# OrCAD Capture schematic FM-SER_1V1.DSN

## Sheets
1 01. INDEX: title: FM-SER    01. INDEX; rev: 1.1; note: 8000012001
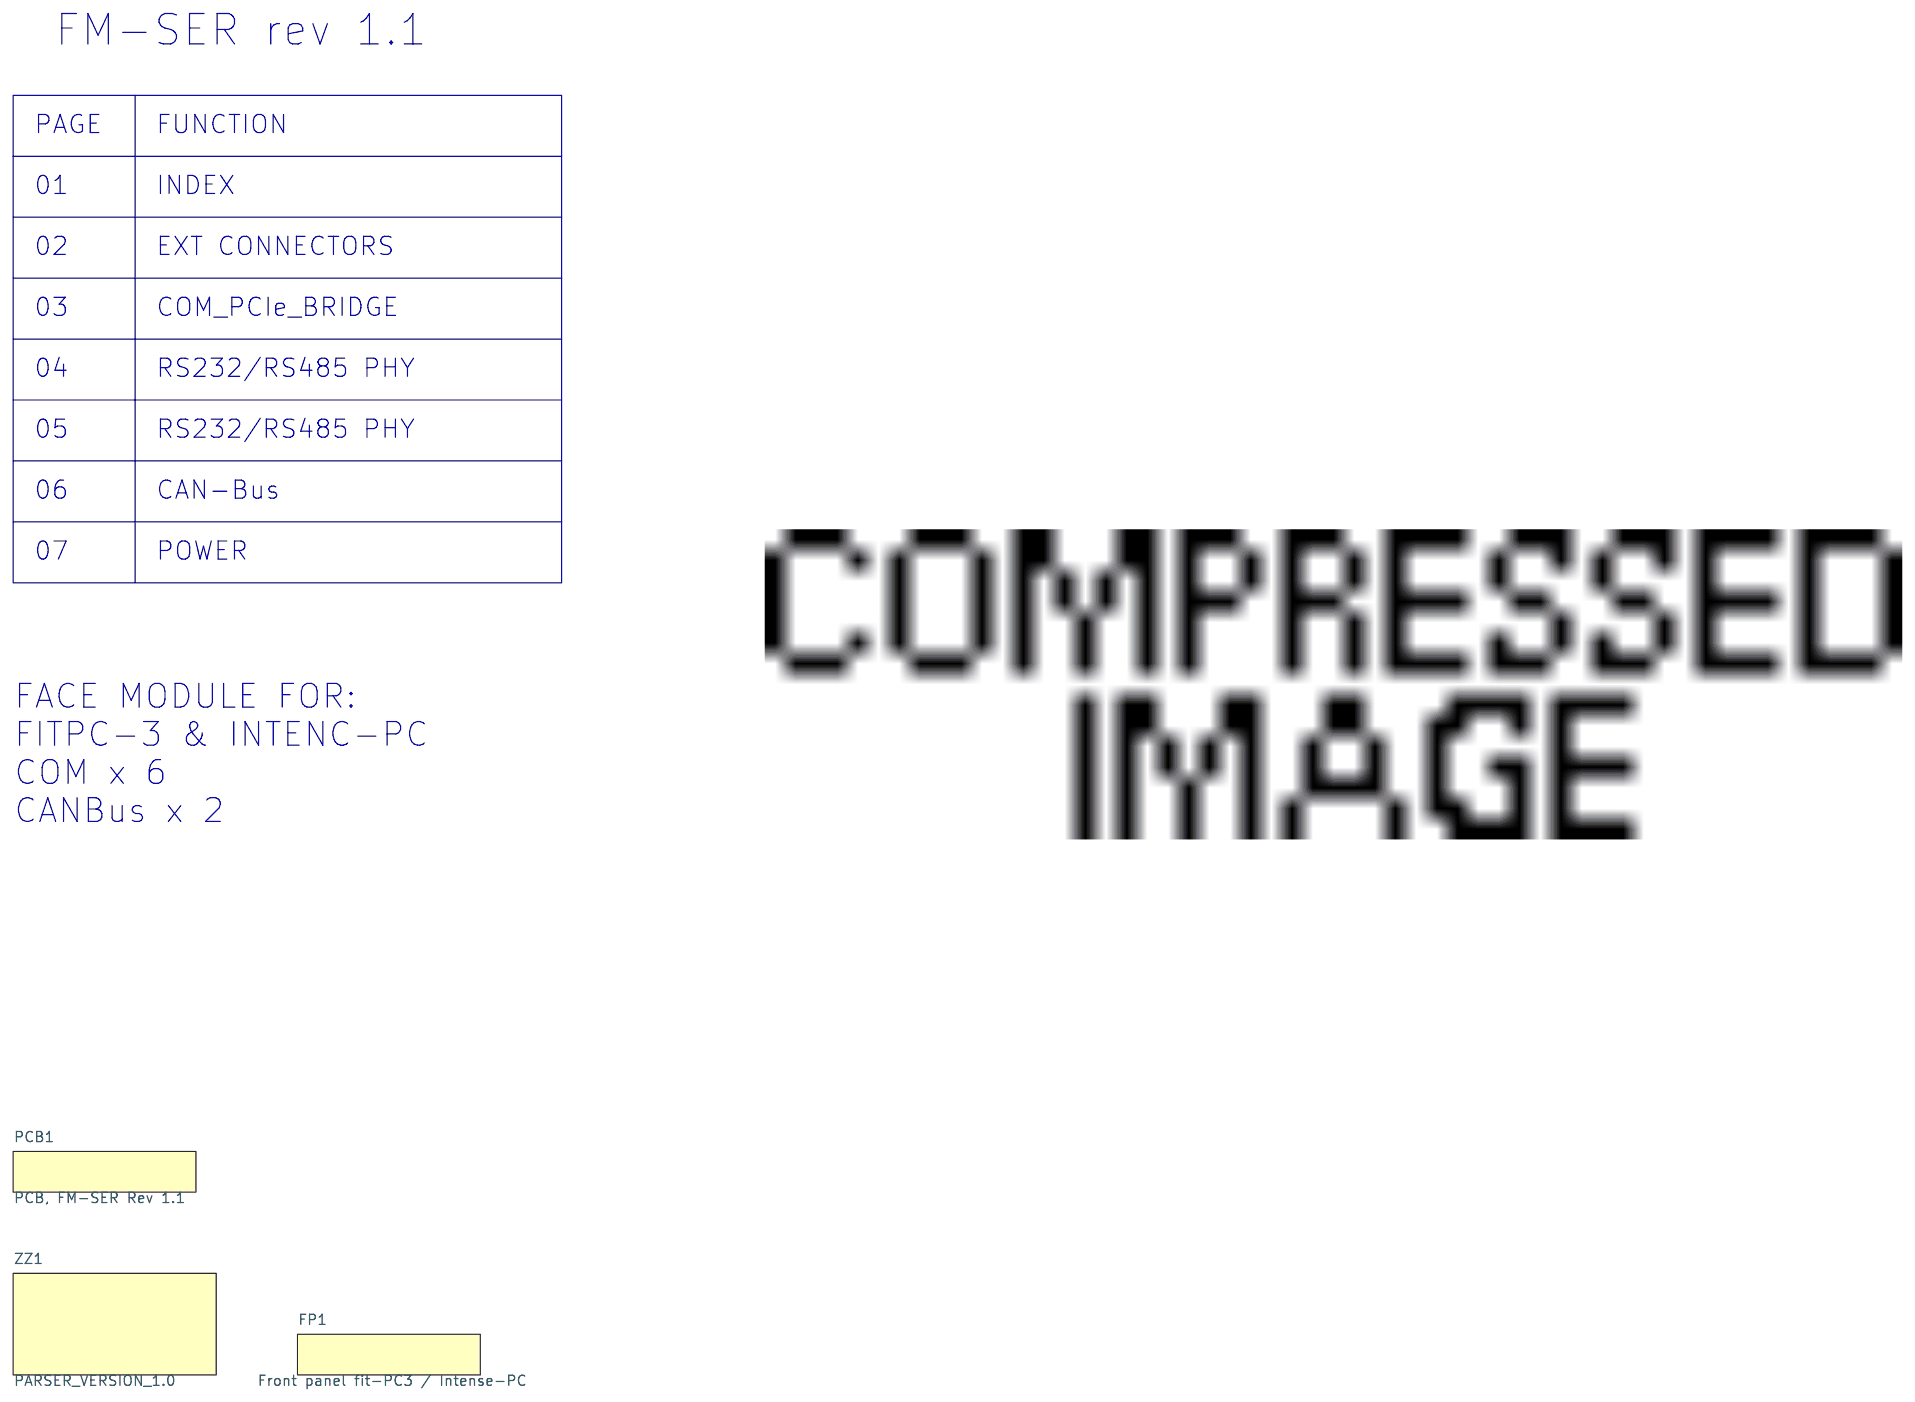
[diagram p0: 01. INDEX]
2 02. EXT CONN: size B; title: FM-SER    02. EXT_CONN
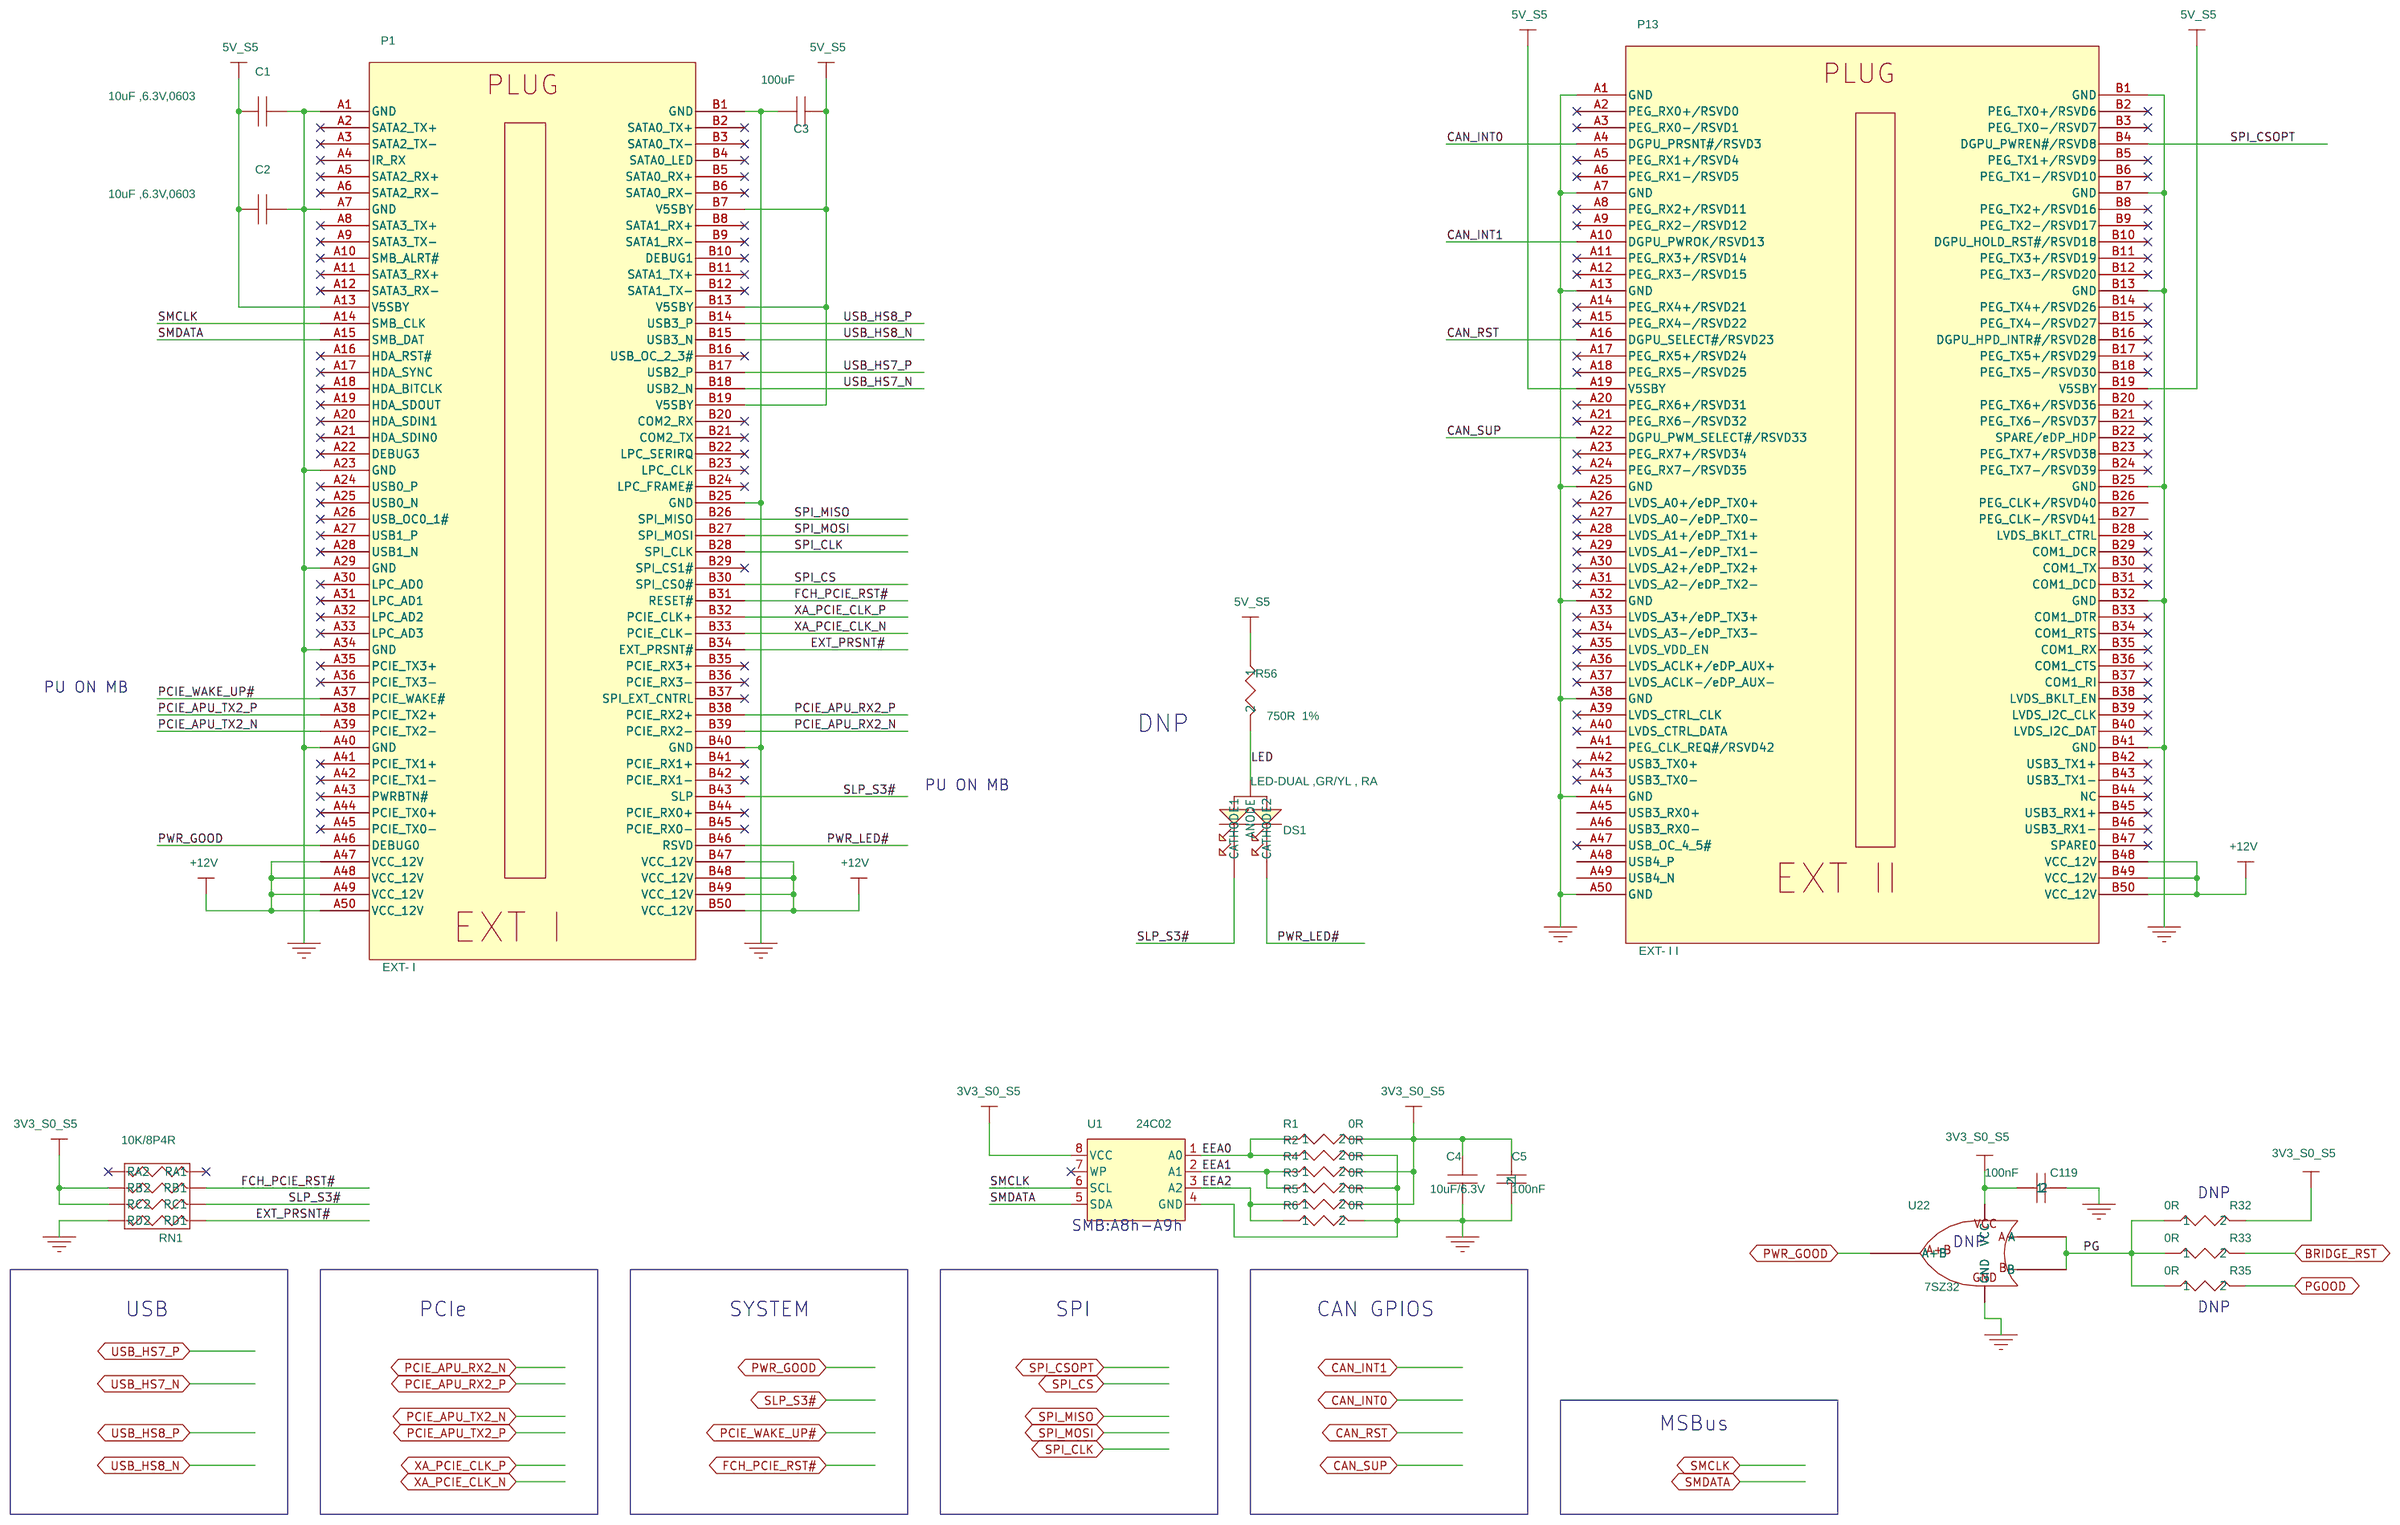
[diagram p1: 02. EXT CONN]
3 03. COM_PCIe_BRIDGE: size B; title: FM-SER  03. COM_PCIe_BRIDGE
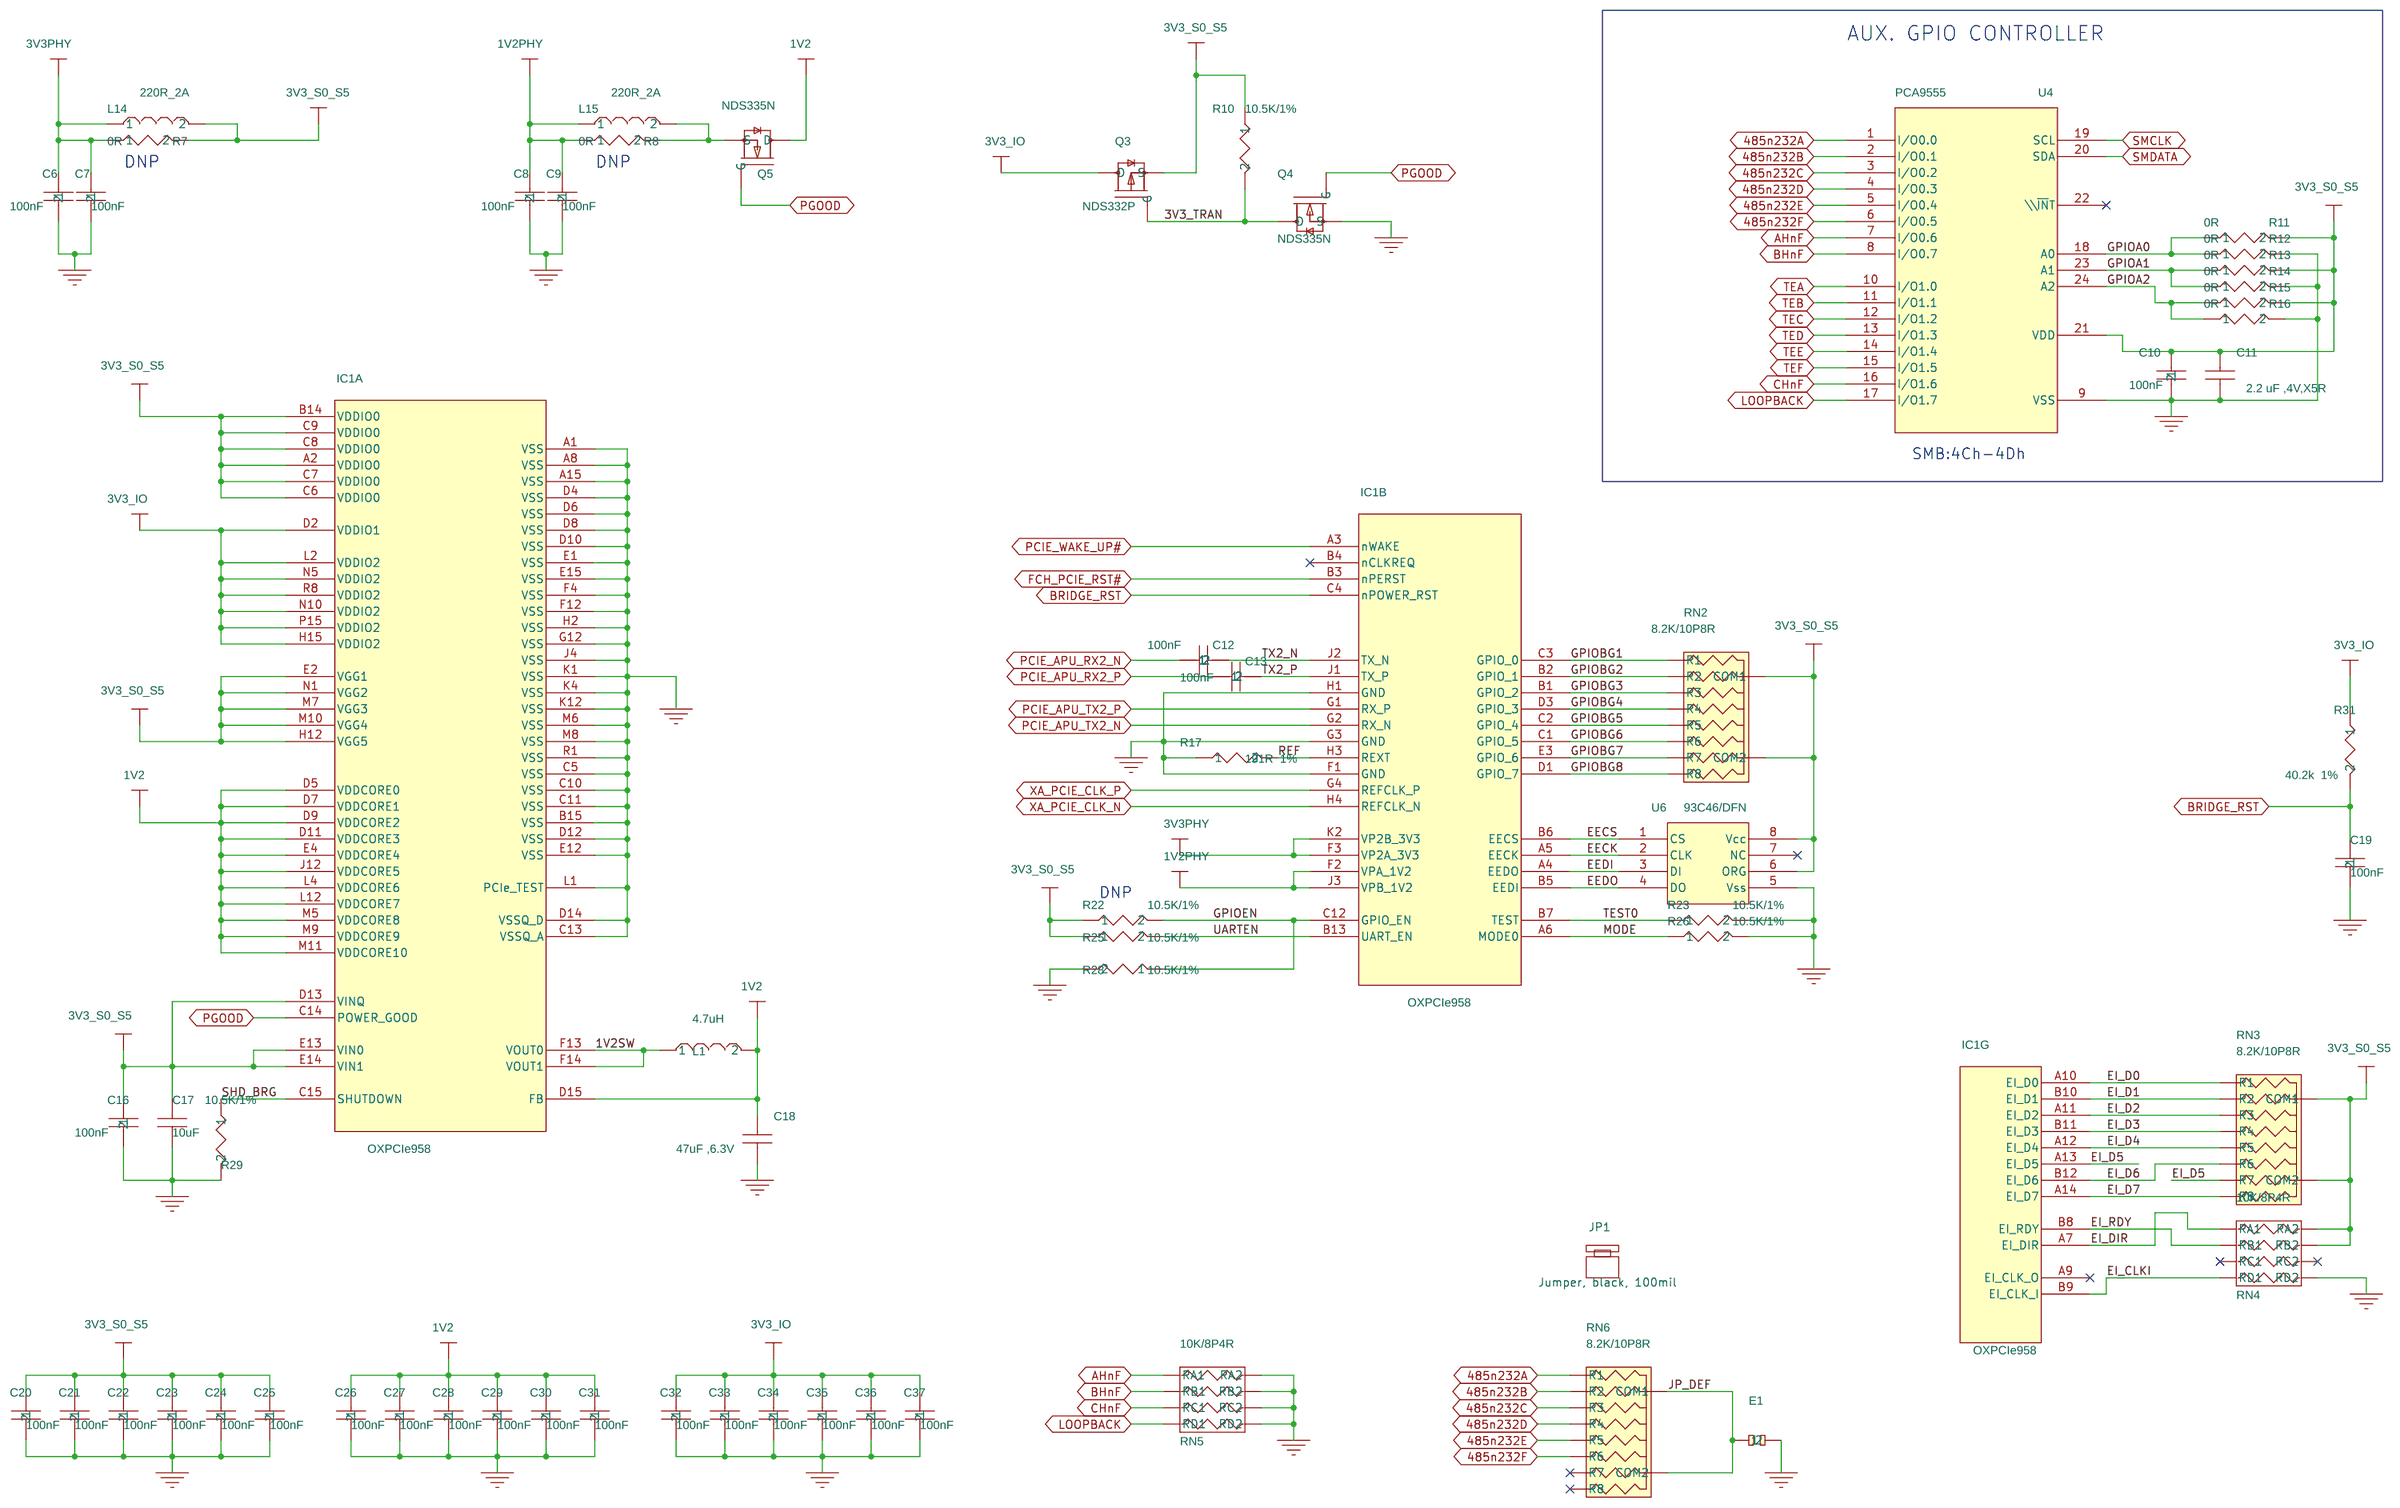
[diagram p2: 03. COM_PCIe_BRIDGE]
4 06. CAN Bus: size C; title: FM-SER    06. POWER
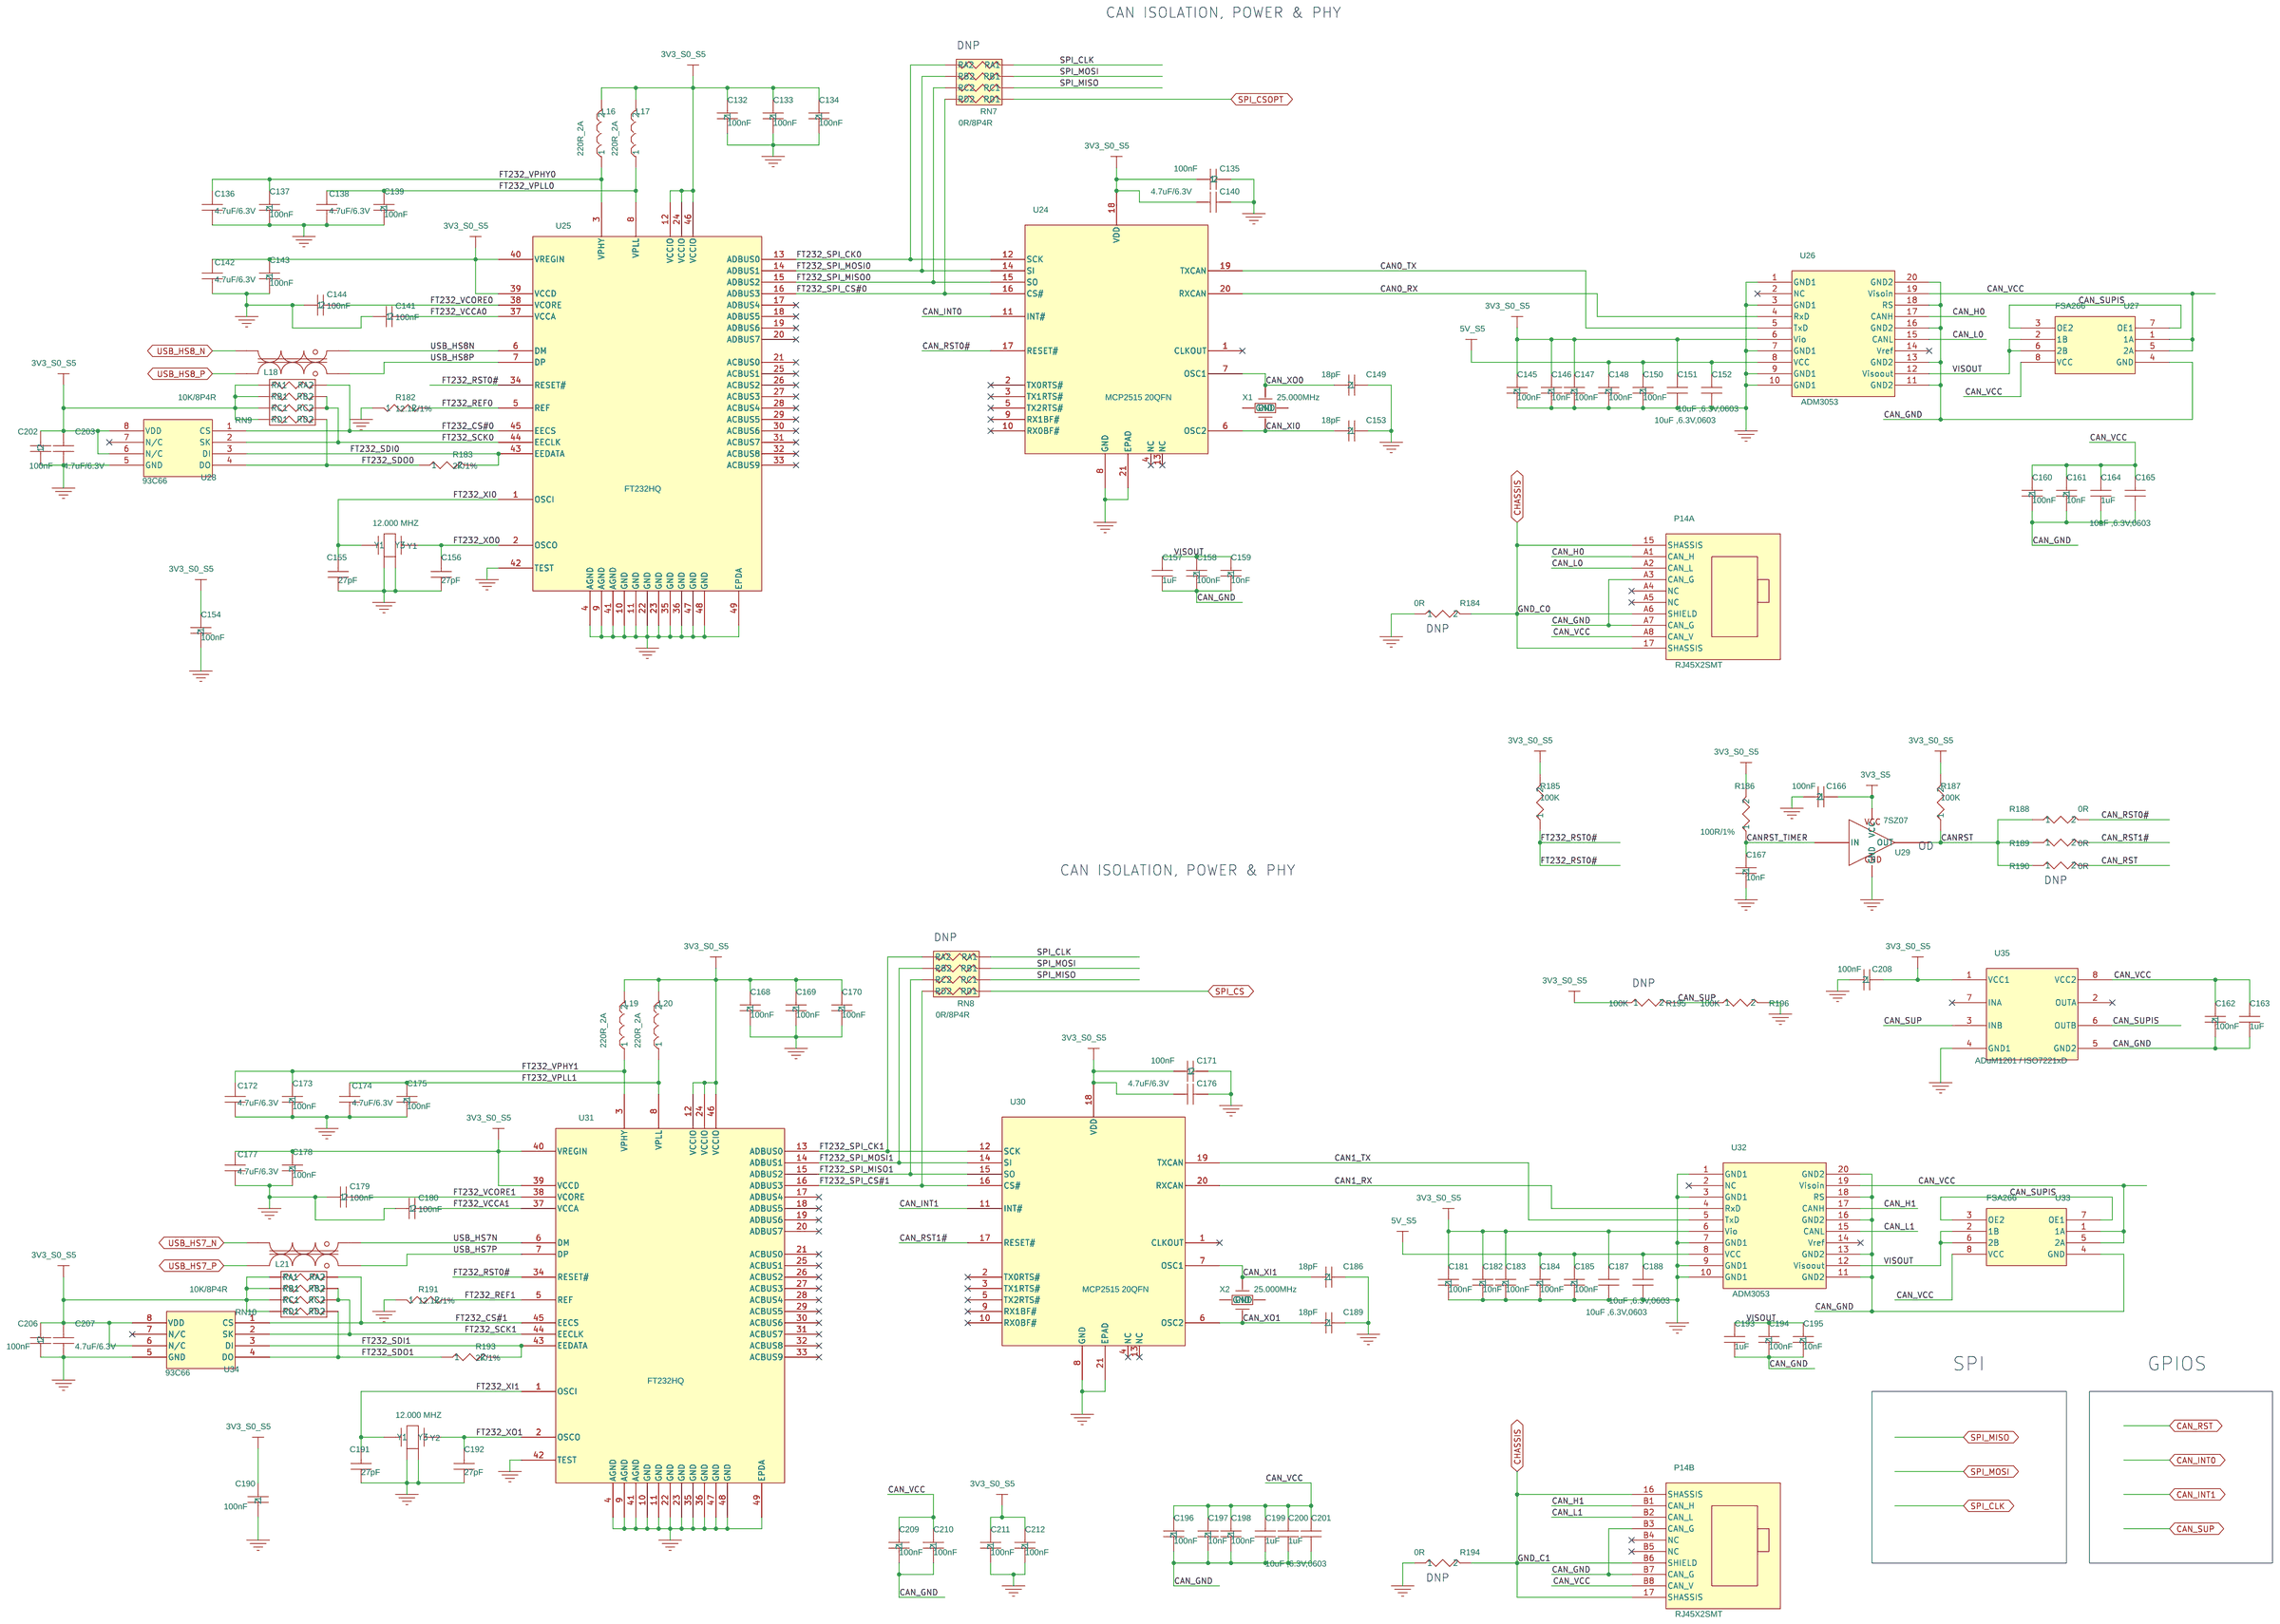
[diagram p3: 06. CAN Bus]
5 07. POWER: size B; title: FM-SER    06. POWER
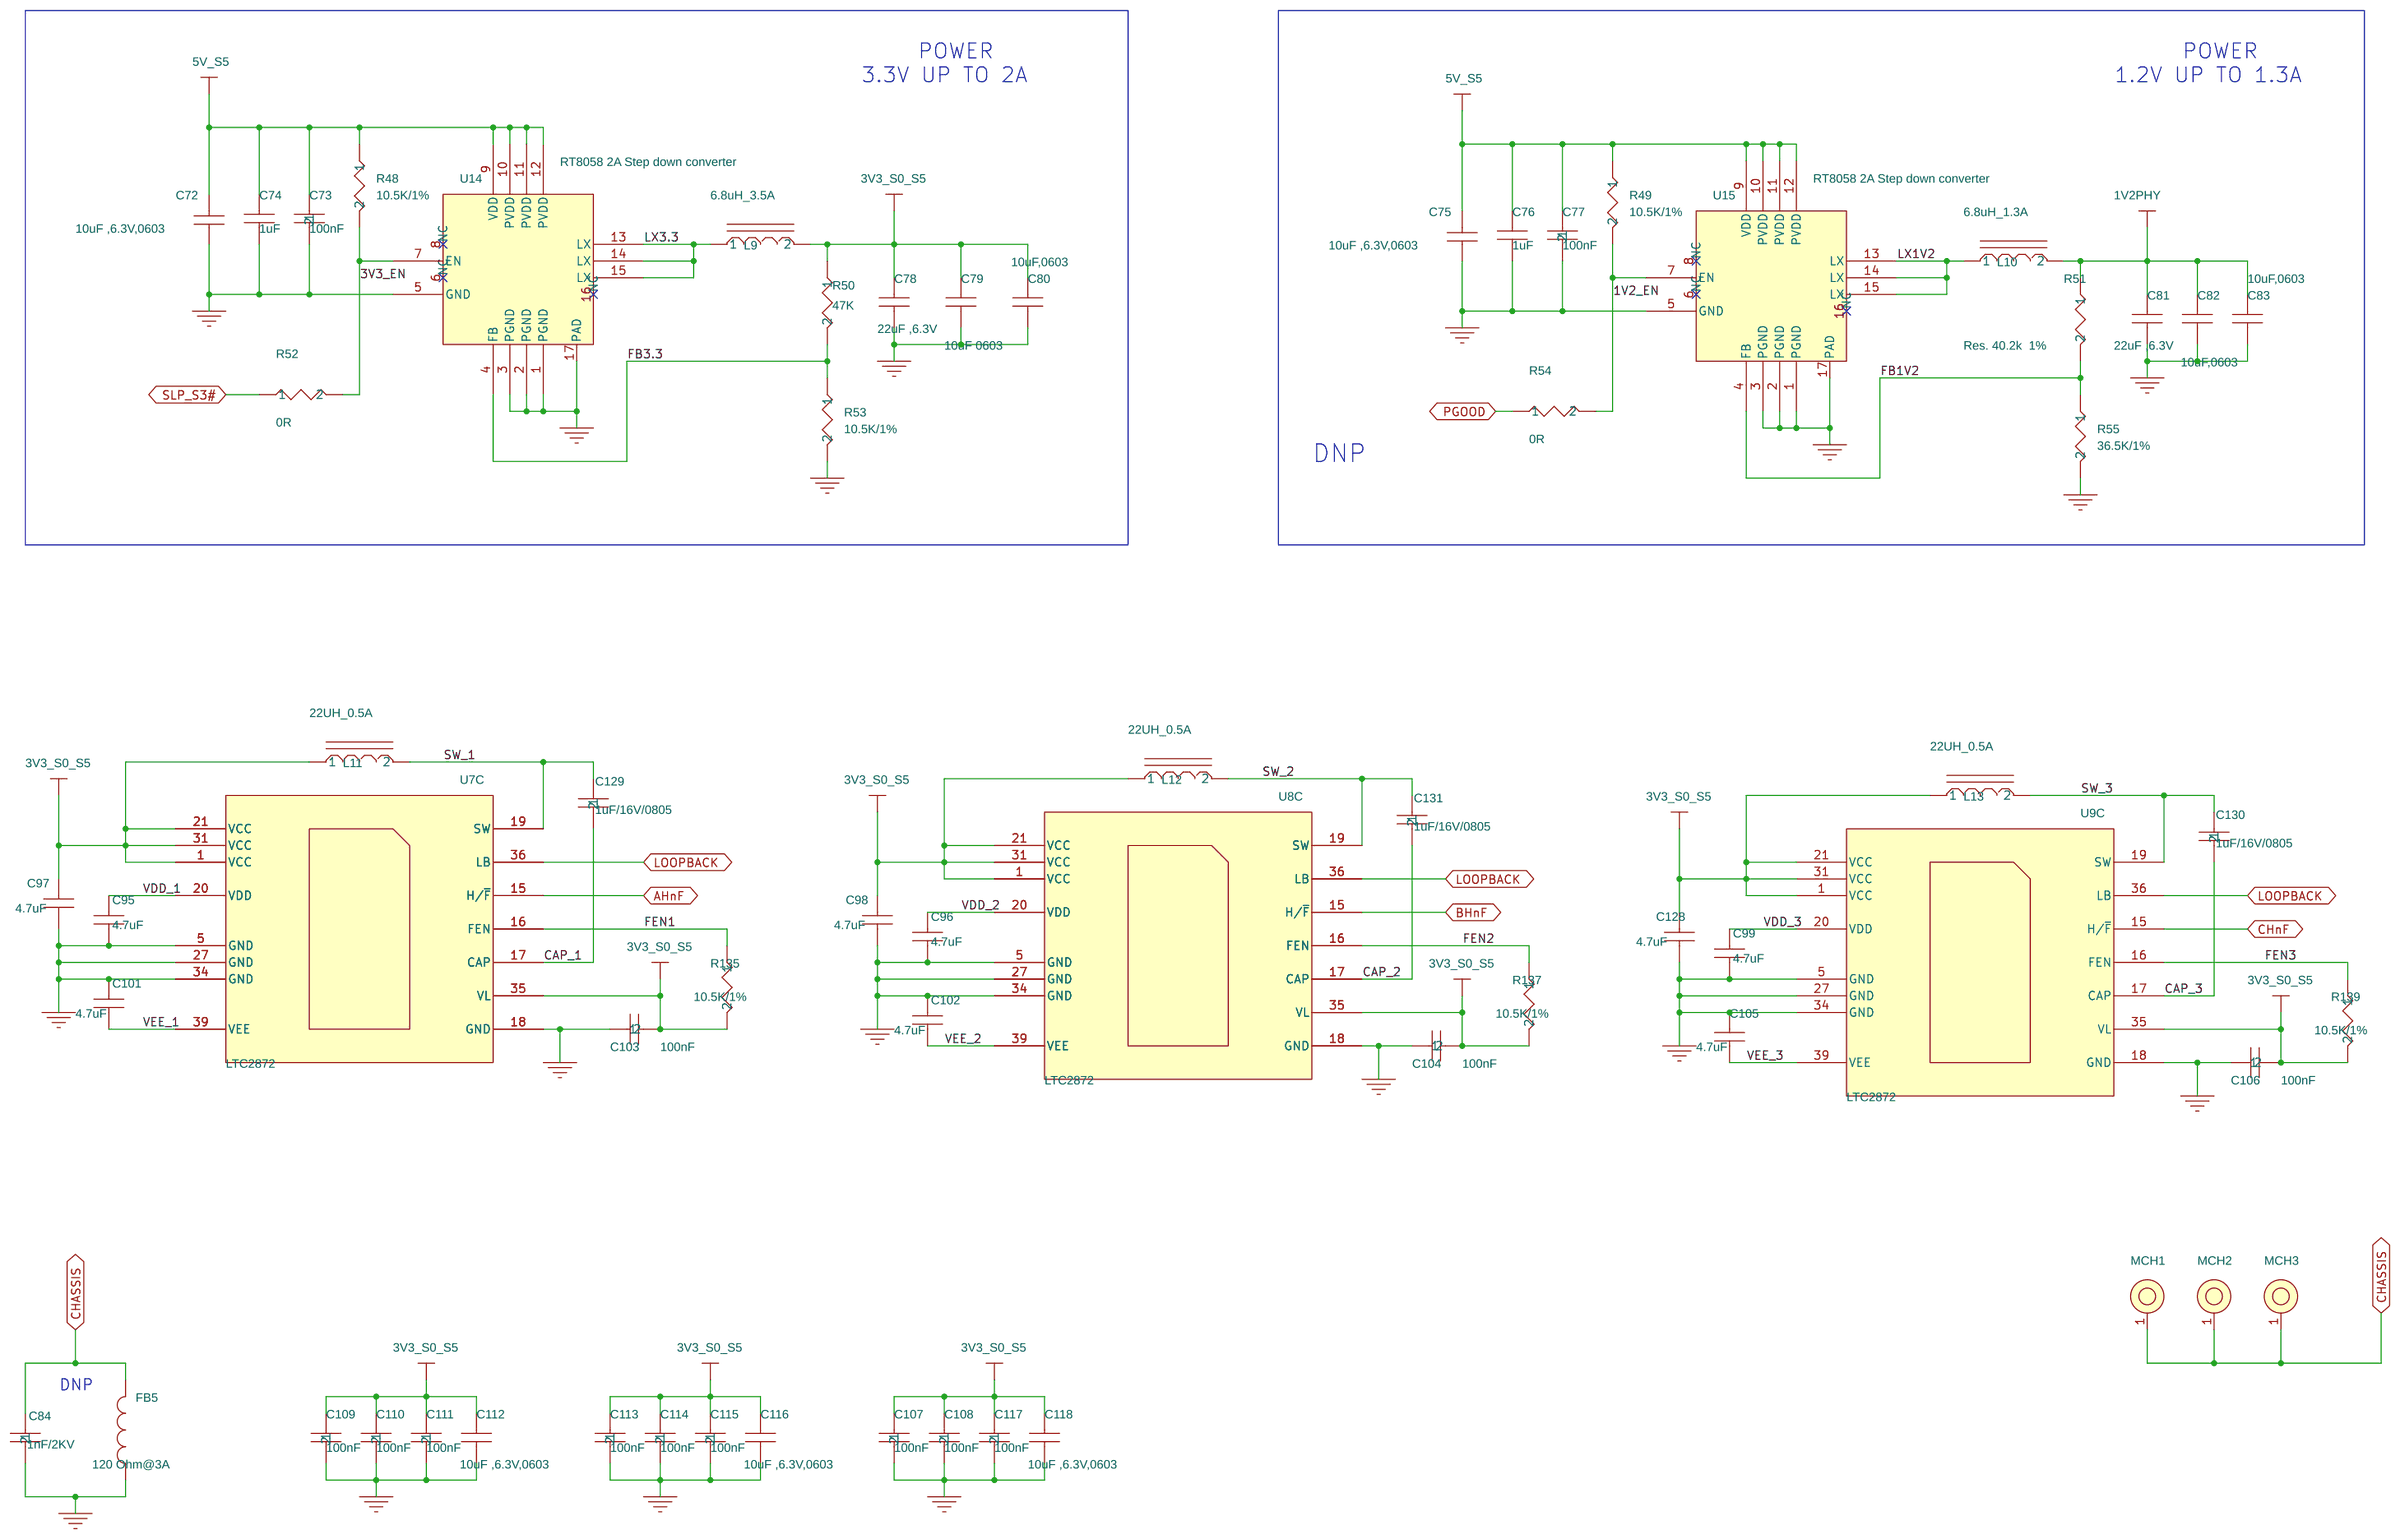
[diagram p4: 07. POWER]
6 04. RS232/RS485 PHY: size B; title: FM-SER    04.RS232/RS485 PHY
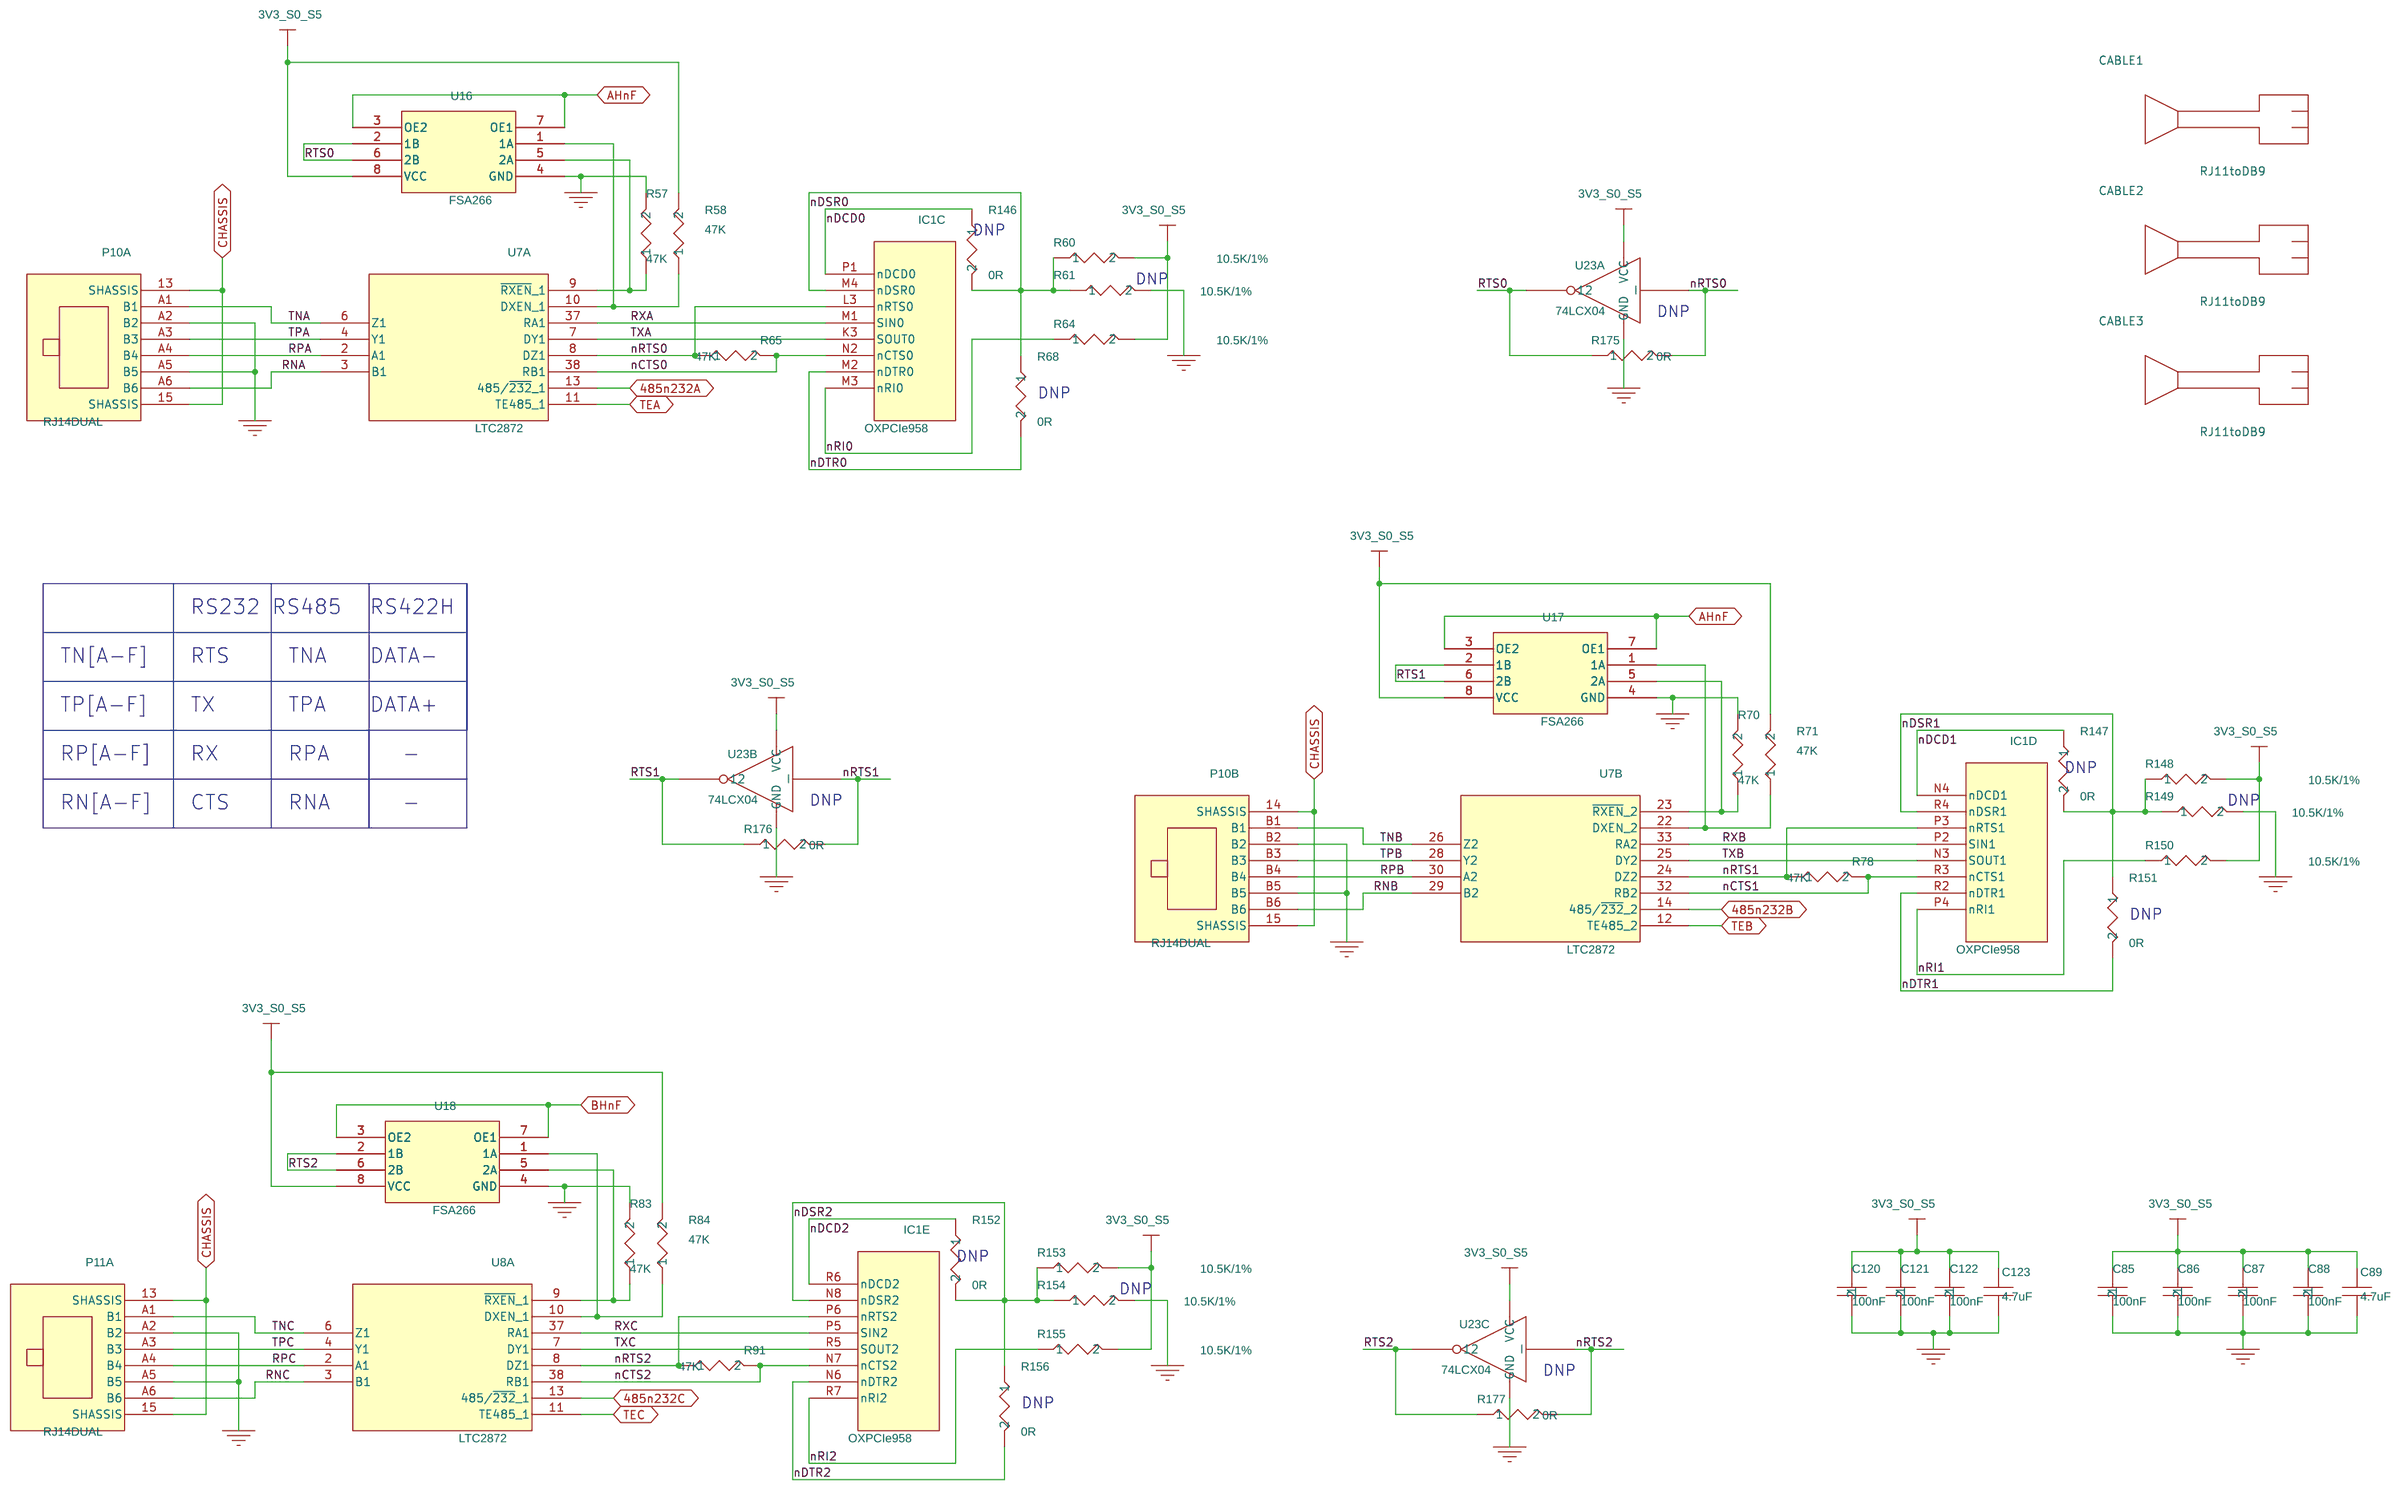
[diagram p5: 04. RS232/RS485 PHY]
7 05. RS232/RS485 PHY: size B; title: FM-SER    04.RS232/RS485 PHY
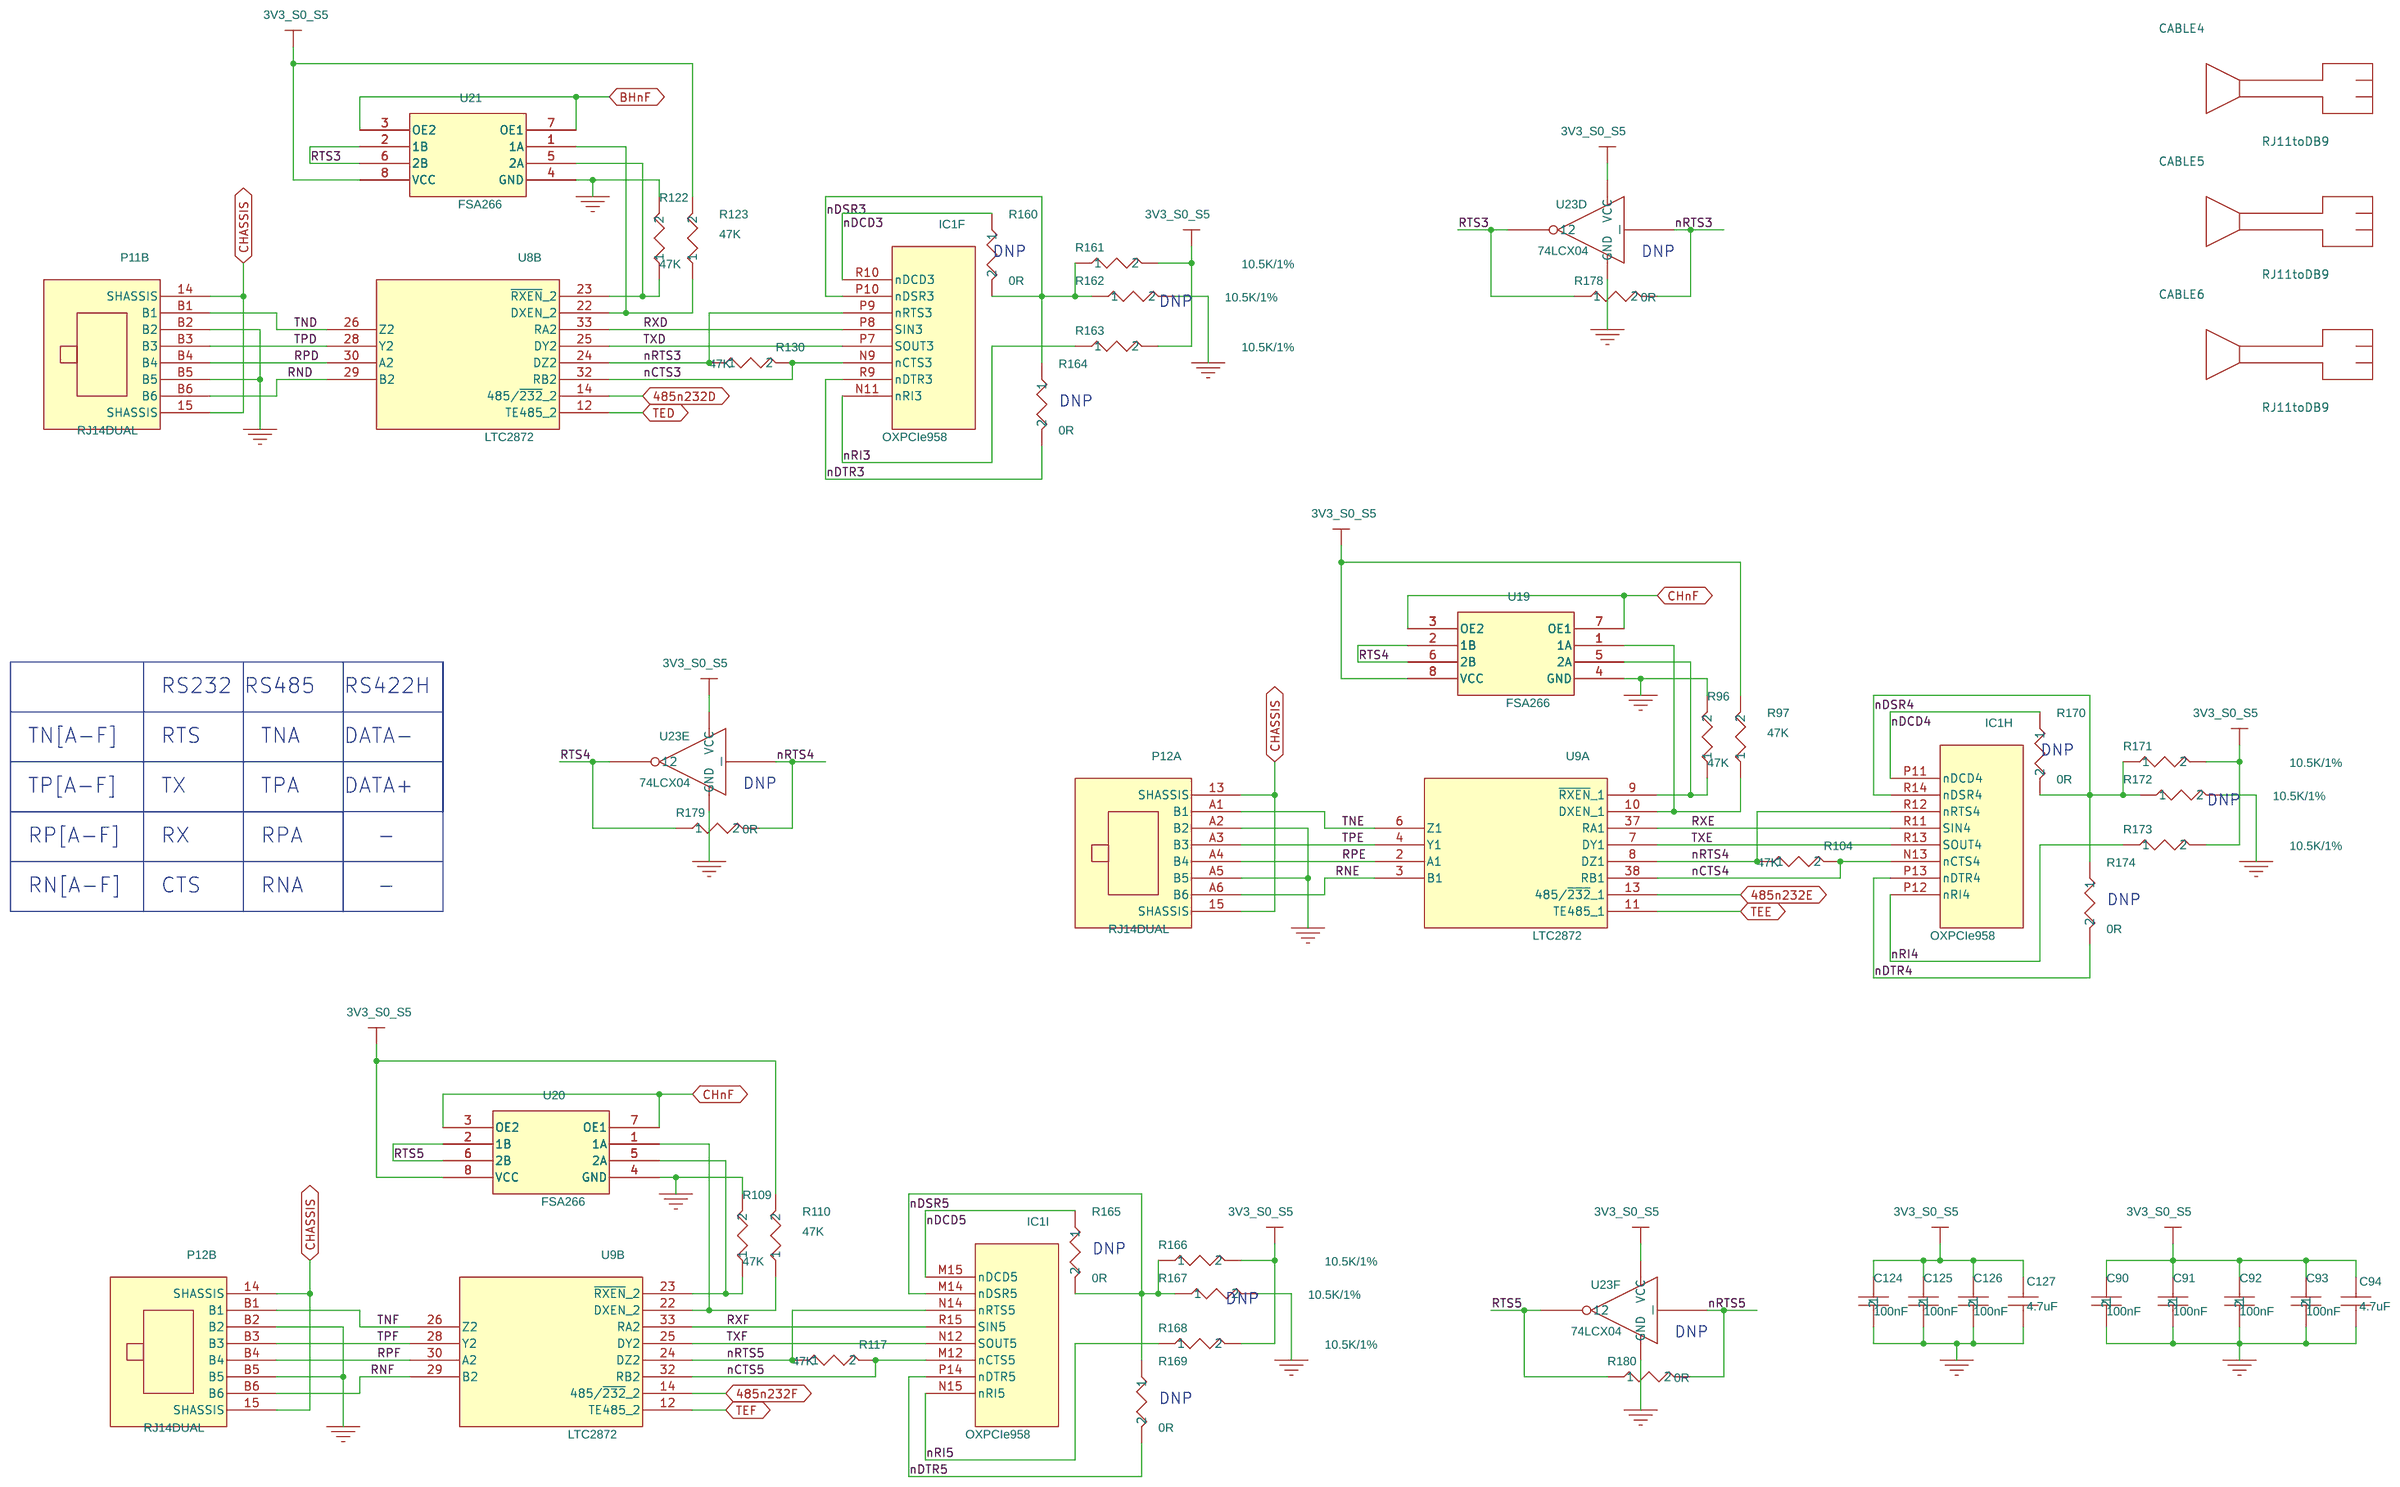
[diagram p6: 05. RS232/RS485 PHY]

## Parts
sheet 01. INDEX
FP1  Front panel fit-PC3 / Intense-PC
PCB1  PCB, FM-SER Rev 1.1
ZZ1  PARSER_VERSION_1.0
sheet 02. EXT CONN
C1  10uF ,6.3V,0603  [RC0603]
C2  10uF ,6.3V,0603  [RC0603]
C3  100uF  [C1210H2_5]
C4  10uF/6.3V  [RC0603]
C5  100nF  [RC0402]
C119  100nF  [RC0402]
DS1  LED-DUAL ,GR/YL , RA  [LED3x1RASM]
P1  EXT- I  [B2B08M2X50P]
P13  EXT- I I  [B2B08M2X50P]
R1  0R  [RC0402]
R2  0R  [RC0402]
R3  0R  [RC0402]
R4  0R  [RC0402]
R5  0R  [RC0402]
R6  0R  [RC0402]
R32  0R  [RC0402]
R33  0R  [RC0402]
R35  0R  [RC0402]
R56  750R  1%  [RC0402]
RN1  10K/8P4R  [RESNET8P0805]
U1  24C02  [MO-229VCED-2]
U22  7SZ32  [SC70]
sheet 03. COM_PCIe_BRIDGE
C6  100nF  [RC0402]
C7  100nF  [RC0402]
C8  100nF  [RC0402]
C9  100nF  [RC0402]
C10  100nF  [RC0402]
C11  2.2 uF ,4V,X5R  [RC0402]
C12  100nF  [RC0402]
C13  100nF  [RC0402]
C16  100nF  [RC0402]
C17  10uF  [RC0603]
C18  47uF ,6.3V  [C0805]
C19  100nF  [RC0402]
C20  100nF  [RC0402]
C21  100nF  [RC0402]
C22  100nF  [RC0402]
C23  100nF  [RC0402]
C24  100nF  [RC0402]
C25  100nF  [RC0402]
C26  100nF  [RC0402]
C27  100nF  [RC0402]
C28  100nF  [RC0402]
C29  100nF  [RC0402]
C30  100nF  [RC0402]
C31  100nF  [RC0402]
C32  100nF  [RC0402]
C33  100nF  [RC0402]
C34  100nF  [RC0402]
C35  100nF  [RC0402]
C36  100nF  [RC0402]
C37  100nF  [RC0402]
E1  HDR1X2  [1X2THRAHDR]
JP1  Jumper, black, 100mil
L1  4.7uH  [IND5x5x2_5]
L14  220R_2A  [FB0603]
L15  220R_2A  [FB0603]
Q3  NDS332P  [SOT23]
Q4  NDS335N  [SOT23]
Q5  NDS335N  [SOT23]
R7  0R  [RC0402]
R8  0R  [RC0402]
R10  10.5K/1%  [RC0402]
R11  0R  [RC0402]
R12  0R  [RC0402]
R13  0R  [RC0402]
R14  0R  [RC0402]
R15  0R  [RC0402]
R16  0R  [RC0402]
R17  191R  1%  [RC0402]
R22  10.5K/1%  [RC0402]
R23  10.5K/1%  [RC0402]
R25  10.5K/1%  [RC0402]
R26  10.5K/1%  [RC0402]
R28  10.5K/1%  [RC0402]
R29  10.5K/1%  [RC0402]
R31  40.2k  1%  [RC0402]
RN2  8.2K/10P8R  [RESNET10P1206]
RN3  8.2K/10P8R  [RESNET10P1206]
RN4  10K/8P4R  [RESNET8P0805]
RN5  10K/8P4R  [RESNET8P0805]
RN6  8.2K/10P8R  [RESNET10P1206]
U4  PCA9555  [QFN4x4-24]
U6  93C46/DFN  [MO-229VCED-2]
sheet 04. RS232/RS485 PHY
C85  100nF  [RC0402]
C86  100nF  [RC0402]
C87  100nF  [RC0402]
C88  100nF  [RC0402]
C89  4.7uF  [C0603-08]
C120  100nF  [RC0402]
C121  100nF  [RC0402]
C122  100nF  [RC0402]
C123  4.7uF  [C0603-08]
CABLE1  RJ11toDB9
CABLE2  RJ11toDB9
CABLE3  RJ11toDB9
IC1  OXPCIe958  [BGA-176-08-13x13]  (sections A,B,C,D,E,F,G,H,I)
P10  RJ14DUAL  [RJ11SM6-6X2]  (sections A,B)
R57  47K  [RC0402]
R58  47K  [RC0402]
R60  10.5K/1%  [RC0402]
R61  10.5K/1%  [RC0402]
R64  10.5K/1%  [RC0402]
R65  47K  [RC0402]
R68  0R  [RC0402]
R70  47K  [RC0402]
R71  47K  [RC0402]
R78  47K  [RC0402]
R83  47K  [RC0402]
R84  47K  [RC0402]
R91  47K  [RC0402]
R146  0R  [RC0402]
R147  0R  [RC0402]
R148  10.5K/1%  [RC0402]
R149  10.5K/1%  [RC0402]
R150  10.5K/1%  [RC0402]
R151  0R  [RC0402]
R152  0R  [RC0402]
R153  10.5K/1%  [RC0402]
R154  10.5K/1%  [RC0402]
R155  10.5K/1%  [RC0402]
R156  0R  [RC0402]
R175  0R  [RC0402]
R176  0R  [RC0402]
R177  0R  [RC0402]
U7  LTC2872  [MO-220WHKD]  (sections A,B,C)
U8  LTC2872  [MO-220WHKD]  (sections A,B,C)
U16  FSA266  [MO-187CA-8]
U17  FSA266  [MO-187CA-8]
U18  FSA266  [MO-187CA-8]
sheet 05. RS232/RS485 PHY
C90  100nF  [RC0402]
C91  100nF  [RC0402]
C92  100nF  [RC0402]
C93  100nF  [RC0402]
C94  4.7uF  [C0603-08]
C124  100nF  [RC0402]
C125  100nF  [RC0402]
C126  100nF  [RC0402]
C127  4.7uF  [C0603-08]
CABLE4  RJ11toDB9
CABLE5  RJ11toDB9
CABLE6  RJ11toDB9
P11  RJ14DUAL  [RJ11SM6-6X2]  (sections A,B)
P12  RJ14DUAL  [RJ11SM6-6X2]  (sections A,B)
R96  47K  [RC0402]
R97  47K  [RC0402]
R104  47K  [RC0402]
R109  47K  [RC0402]
R110  47K  [RC0402]
R117  47K  [RC0402]
R122  47K  [RC0402]
R123  47K  [RC0402]
R130  47K  [RC0402]
R160  0R  [RC0402]
R161  10.5K/1%  [RC0402]
R162  10.5K/1%  [RC0402]
R163  10.5K/1%  [RC0402]
R164  0R  [RC0402]
R165  0R  [RC0402]
R166  10.5K/1%  [RC0402]
R167  10.5K/1%  [RC0402]
R168  10.5K/1%  [RC0402]
R169  0R  [RC0402]
R170  0R  [RC0402]
R171  10.5K/1%  [RC0402]
R172  10.5K/1%  [RC0402]
R173  10.5K/1%  [RC0402]
R174  0R  [RC0402]
R178  0R  [RC0402]
R179  0R  [RC0402]
R180  0R  [RC0402]
U19  FSA266  [MO-187CA-8]
U20  FSA266  [MO-187CA-8]
U21  FSA266  [MO-187CA-8]
U23  74LCX04  [TSSOP-14]  (sections A,B,C,D,E,F)
sheet 06. CAN Bus
C132  100nF  [RC0402]
C133  100nF  [RC0402]
C134  100nF  [RC0402]
C135  100nF  [RC0402]
C136  4.7uF/6.3V  [C0603-08]
C137  100nF  [RC0402]
C138  4.7uF/6.3V  [C0603-08]
C139  100nF  [RC0402]
C140  4.7uF/6.3V  [C0603-08]
C141  100nF  [RC0402]
C142  4.7uF/6.3V  [C0603-08]
C143  100nF  [RC0402]
C144  100nF  [RC0402]
C145  100nF  [RC0402]
C146  10nF  [RC0402]
C147  100nF  [RC0402]
C148  100nF  [RC0402]
C149  18pF  [RC0402]
C150  100nF  [RC0402]
C151  10uF ,6.3V,0603  [RC0603]
C152  10uF ,6.3V,0603  [RC0603]
C153  18pF  [RC0402]
C154  100nF  [RC0402]
C155  27pF  [RC0402]
C156  27pF  [RC0402]
C157  1uF  [RC0402]
C158  100nF  [RC0402]
C159  10nF  [RC0402]
C160  100nF  [RC0402]
C161  10nF  [RC0402]
C162  100nF  [RC0402]
C163  1uF  [RC0402]
C164  1uF  [RC0402]
C165  10uF ,6.3V,0603  [RC0603]
C166  100nF  [RC0402]
C167  10nF  [RC0402]
C168  100nF  [RC0402]
C169  100nF  [RC0402]
C170  100nF  [RC0402]
C171  100nF  [RC0402]
C172  4.7uF/6.3V  [C0603-08]
C173  100nF  [RC0402]
C174  4.7uF/6.3V  [C0603-08]
C175  100nF  [RC0402]
C176  4.7uF/6.3V  [C0603-08]
C177  4.7uF/6.3V  [C0603-08]
C178  100nF  [RC0402]
C179  100nF  [RC0402]
C180  100nF  [RC0402]
C181  100nF  [RC0402]
C182  10nF  [RC0402]
C183  100nF  [RC0402]
C184  100nF  [RC0402]
C185  100nF  [RC0402]
C186  18pF  [RC0402]
C187  10uF ,6.3V,0603  [RC0603]
C188  10uF ,6.3V,0603  [RC0603]
C189  18pF  [RC0402]
C190  100nF  [RC0402]
C191  27pF  [RC0402]
C192  27pF  [RC0402]
C193  1uF  [RC0402]
C194  100nF  [RC0402]
C195  10nF  [RC0402]
C196  100nF  [RC0402]
C197  10nF  [RC0402]
C198  100nF  [RC0402]
C199  1uF  [RC0402]
C200  1uF  [RC0402]
C201  10uF ,6.3V,0603  [RC0603]
C202  100nF  [RC0402]
C203  4.7uF/6.3V  [C0603-08]
C206  100nF  [RC0402]
C207  4.7uF/6.3V  [C0603-08]
C208  100nF  [RC0402]
C209  100nF  [RC0402]
C210  100nF  [RC0402]
C211  100nF  [RC0402]
C212  100nF  [RC0402]
L16  220R_2A  [FB0603]
L17  220R_2A  [FB0603]
L18  MURATA_DLP11SN900SL2  [EMO1012]
L19  220R_2A  [FB0603]
L20  220R_2A  [FB0603]
L21  MURATA_DLP11SN900SL2  [EMO1012]
P14  RJ45X2SMT  [RJ45SM8-8X2]  (sections A,B)
R182  12.1K/1%  [RC0402]
R183  2K/1%  [RC0402]
R184  0R  [RC1206]
R185  100K  [RC0402]
R186  100R/1%  [RC0402]
R187  100K  [RC0402]
R188  0R  [RC0402]
R189  0R  [RC0402]
R190  0R  [RC0402]
R191  12.1K/1%  [RC0402]
R193  2K/1%  [RC0402]
R194  0R  [RC1206]
R195  100K  [RC0402]
R196  100K  [RC0402]
RN7  0R/8P4R  [RESNET8P0805]
RN8  0R/8P4R  [RESNET8P0805]
RN9  10K/8P4R  [RESNET8P0805]
RN10  10K/8P4R  [RESNET8P0805]
U24  MCP2515 20QFN  [MO-220WGGD-5]
U25  FT232HQ  [MO-220VLLD-3]
U26  ADM3053  [SOIC-20]
U27  FSA266  [MO-187CA-8]
U28  93C66  [MO-229VCED-2]
U29  7SZ07  [SC70]
U30  MCP2515 20QFN  [MO-220WGGD-5]
U31  FT232HQ  [MO-220VLLD-3]
U32  ADM3053  [SOIC-20]
U33  FSA266  [MO-187CA-8]
U34  93C66  [MO-229VCED-2]
U35  ADuM1201 / ISO7221xD  [SO-8-150]
X1  25.000MHz  [XTAL5x3-4]
X2  25.000MHz  [XTAL5x3-4]
Y1  12.000 MHZ  [XTAL5x3-4]
Y2  12.000 MHZ  [XTAL5x3-4]
sheet 07. POWER
C72  10uF ,6.3V,0603  [RC0603]
C73  100nF  [RC0402]
C74  1uF  [RC0402]
C75  10uF ,6.3V,0603  [RC0603]
C76  1uF  [RC0402]
C77  100nF  [RC0402]
C78  22uF ,6.3V  [0805]
C79  10uF 0603  [RC0603]
C80  10uF,0603  [RC0603]
C81  22uF ,6.3V  [0805]
C82  10uF,0603  [RC0603]
C83  10uF,0603  [RC0603]
C84  1nF/2KV  [C1812]
C95  4.7uF  [C0805]
C96  4.7uF  [C0805]
C97  4.7uF  [C0603-08]
C98  4.7uF  [C0603-08]
C99  4.7uF  [C0805]
C101  4.7uF  [C0805]
C102  4.7uF  [C0805]
C103  100nF  [RC0402]
C104  100nF  [RC0402]
C105  4.7uF  [C0805]
C106  100nF  [RC0402]
C107  100nF  [RC0402]
C108  100nF  [RC0402]
C109  100nF  [RC0402]
C110  100nF  [RC0402]
C111  100nF  [RC0402]
C112  10uF ,6.3V,0603  [RC0603]
C113  100nF  [RC0402]
C114  100nF  [RC0402]
C115  100nF  [RC0402]
C116  10uF ,6.3V,0603  [RC0603]
C117  100nF  [RC0402]
C118  10uF ,6.3V,0603  [RC0603]
C128  4.7uF  [C0603-08]
C129  1uF/16V/0805  [RC0603]
C130  1uF/16V/0805  [RC0603]
C131  1uF/16V/0805  [RC0603]
FB5  120 Ohm@3A  [1206]
L9  6.8uH_3.5A  [IND8_2x8_2]
L10  6.8uH_1.3A  [IND4x4_5x3_2S]
L11  22UH_0.5A  [IND4x4_5x3_2S]
L12  22UH_0.5A  [IND4x4_5x3_2S]
L13  22UH_0.5A  [IND4x4_5x3_2S]
MCH1  MechHole  [3,5X6,5]
MCH2  MechHole  [3,5X6,5]
MCH3  MechHole  [3,5X6,5]
R48  10.5K/1%  [RC0402]
R49  10.5K/1%  [RC0402]
R50  47K  [RC0402]
R51  Res. 40.2k  1%  [0402]
R52  0R  [RC0402]
R53  10.5K/1%  [RC0402]
R54  0R  [RC0402]
R55  36.5K/1%  [RC0402]
R135  10.5K/1%  [RC0402]
R137  10.5K/1%  [RC0402]
R139  10.5K/1%  [RC0402]
U9  LTC2872  [MO-220WHKD]  (sections A,B,C)
U14  RT8058 2A Step down converter  [WQFN-16L3x3]
U15  RT8058 2A Step down converter  [WQFN-16L3x3]

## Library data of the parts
FP1 = PCB,_EM-X270_Rev_1_0.1: CLABCONF0: 373D30010 = NOT FPM AND NOT Y; CLABCONF1: 373D30012 = FPM; CLABCONF2: 373D30015= Y AND NOT FPM; P/N: 373D30010
PCB1 = PCB,_EM-X270_Rev_1_0.1: CLABCONF0: =FM-SER; P/N: 188C02431
ZZ1 = PARSER_VERSION_1_1.0
C1 = 10uF,6.3V,0603,X5R_1: CLABCONF0: =FM-SER
C2 C80 = 10uF,6.3V,0603,X5R: CLABCONF0: =FM-SER
C3 = 100uF,_6.3V,_X5R,_20%,_1210: CLABCONF0: =FM-SER
C4 = Cap.,10uF,6.3V,0603,X5R: CLABCONF0: =FM-SER
C5 C9 C108 C122 C125 = 100nF,_10V,_X7R,_10%,_0402: CLABCONF0: =FM-SER
C27 C88 C93 C107 C119 = 100nF,_10V,_X7R,_10%,_0402_1: CLABCONF0: =FM-SER
DS1 = LED,_Dual,ip_3x1mm,_R_A,_G_Y: CLABCONF0: =DNP
P1 = Conn.,Plg.,X-I,B2B,2x50,P0.8mm: CLABCONF0: =FM-SER
P13 = Conn.,Plg.,X-II,B2B,2x50,P0.8mm: CLABCONF0: =Y; P/N: 182E10003S
R1 R152 = 0R,_0402_8: CLABCONF0: =DNP
R2 R176 = 0R,_0402_7: CLABCONF0: =FM-SER
R3 R12 = 0R,_0402_5: CLABCONF0: =FM-SER
R4 R11 R156 = 0R,_0402_6: CLABCONF0: =DNP
R5 R13 R175 R178 = 0R,_0402_4: CLABCONF0: =FM-SER
R6 R14 R151 R169 = 0R,_0402_3: CLABCONF0: =DNP
R7 R32 R146 R165 R190 = 0R,_0402_2: CLABCONF0: =DNP
R15 R33 R177 = 0R,_0402_1: CLABCONF0: =FM-SER
R16 R35 R68 R174 = 0R,_0402: CLABCONF0: =DNP
R56 = 750R,1%,0402: CLABCONF0: =DNP
RN1 RN4 RN5 = RN,10K,8P4R@0805: CLABCONF0: =FM-SER
U1 = 24C02,_serial_EE,_2KB,_I2C: CLABCONF0: =FM-SER
U22 = 7SZ32_OR_sgl_SC70: CLABCONF0: = DNP
C6 C117 = 100nF,_10V,_X7R,_10%,_0402_13: CLABCONF0: =FM-SER
C7 C86 C115 C126 = 100nF,_10V,_X7R,_10%,_0402_3: CLABCONF0: =FM-SER
C8 C103 = 100nF,_10V,_X7R,_10%,_0402_9: CLABCONF0: =FM-SER
C10 C111 C121 C124 = 100nF,_10V,_X7R,_10%,_0402_6: CLABCONF0: =FM-SER
C11 = 2.2uF,X5R,4V,0402: CLABCONF0: =FM-SER
C12 = 100nF,_10V,_X7R,_10%,_0402_17: CLABCONF0: =FM-SER
C13 = 100nF,_10V,_X7R,_10%,_0402_16: CLABCONF0: =FM-SER
C16 C110 = 100nF,_10V,_X7R,_10%,_0402_7: CLABCONF0: =FM-SER
C17 = 10uF,6.3V,0603,20%X5R: CLABCONF0: =FM-SER
C18 = 47uF,6.3V,X5R: CLABCONF0: =FM-SER
C19 = 100nF,_10V,_X7R,_10%,_0402_24: CLABCONF0: =FM-SER
C20 = 100nF,_10V,_X7R,_10%,_0402_25: CLABCONF0: =FM-SER
C21 = 100nF,_10V,_X7R,_10%,_0402_15: CLABCONF0: =FM-SER
C22 C85 C91 C114 = 100nF,_10V,_X7R,_10%,_0402_4: CLABCONF0: =FM-SER
C23 = 100nF,_10V,_X7R,_10%,_0402_19: CLABCONF0: =FM-SER
C24 C109 = 100nF,_10V,_X7R,_10%,_0402_10: CLABCONF0: =FM-SER
C25 = 100nF,_10V,_X7R,_10%,_0402_23: CLABCONF0: =FM-SER
C26 C73 = 100nF,_10V,_X7R,_10%,_0402_12: CLABCONF0: =FM-SER
C28 = 100nF,_10V,_X7R,_10%,_0402_18: CLABCONF0: =FM-SER
C29 C87 C92 C106 = 100nF,_10V,_X7R,_10%,_0402_2: CLABCONF0: =FM-SER
C30 = 100nF,_10V,_X7R,_10%,_0402_20: CLABCONF0: =FM-SER
C31 = 100nF,_10V,_X7R,_10%,_0402_11: CLABCONF0: =FM-SER
C32 = 100nF,_10V,_X7R,_10%,_0402_22: CLABCONF0: =FM-SER
C33 C104 = 100nF,_10V,_X7R,_10%,_0402_8: CLABCONF0: =FM-SER
C34 = 100nF,_10V,_X7R,_10%,_0402_26: CLABCONF0: =FM-SER
C35 C90 C113 C120 = 100nF,_10V,_X7R,_10%,_0402_5: CLABCONF0: =FM-SER
C36 = 100nF,_10V,_X7R,_10%,_0402_21: CLABCONF0: =FM-SER
C37 = 100nF,_10V,_X7R,_10%,_0402_14: CLABCONF0: =FM-SER
E1 = HDR_1x2_100MIL_TH_JUMPER: CLABCONF0: =FM-SER; P/N: 190C00201
JP1 = Jumper,_black,_100mil: CLABCONF0: =FM-SER
L1 = Ind,_4.7uH,_30%,_1.2A,_0.07_ohm: CLABCONF0: =FM-SER
L14 = Ferrit_330R@100Mhz,0.2A: CLABCONF0: =FM-SER; P/N: 147D22101S
L15 = Ferrit_330R@100Mhz,0.2A_1: CLABCONF0: =FM-SER; P/N: 147D22101S
Q3 = P-MOSFET,3A,20V,110mOhm@-1.8V: CLABCONF0: =FM-SER
Q4 Q5 = N-MOSFET,NDS335N,100mOhm@2.5V: CLABCONF0: =FM-SER
R8 R160 = 0R,_0402_7: CLABCONF0: =DNP
R10 R48 R64 R168 = 10.5K_1%,0402: CLABCONF0: =FM-SER
R17 = 191R,1%,0402: CLABCONF0: =FM-SER
R22 R49 = 10.5K_1%,0402_5: CLABCONF0: =DNP
R23 R139 R150 = 10.5K_1%,0402_1: CLABCONF0: =FM-SER
R25 R137 R171 = 10.5K_1%,0402_3: CLABCONF0: =FM-SER
R26 R53 R173 = 10.5K_1%,0402_2: CLABCONF0: =FM-SER
R28 R135 R148 = 10.5K_1%,0402_4: CLABCONF0: =FM-SER
R29 R163 = 10.5K_1%,0402_6: CLABCONF0: =FM-SER
R31 = 40.2k_,1%: CLABCONF0: =FM-SER
RN2 RN3 RN6 = RN,8.2K,10P8R@1206: CLABCONF0: =FM-SER
U4 = PCA9555: CLABCONF0: =FM-SER
U6 = EEPROM_93C46_DFN: CLABCONF0: =FM-SER
C89 C94 C97 C98 C123 C127 C128 = 4.7uF,_6.3V,_X5R,_20%,_0603: CLABCONF0: =FM-SER
CABLE1-CABLE6 = CABLE: CLABCONF0: =NOT NC; P/N: 504F010030
IC1 = OXPCIe958_10: CLABCONF0: =FM-SER; P/N: 116B00110S
P10-P12 = RJ14DUAL_6: CLABCONF0: =FM-SER; P/N: 180K00601S
R57 R104 = 47K,_0402_2: CLABCONF0: =FM-SER
R58 R96 = 47K,_0402_1: CLABCONF0: =FM-SER
R60 R161 = 10.5K_1%,0402_5: CLABCONF0: =FM-SER
R61 = 10.5K_1%,0402_2: CLABCONF0: =DNP
R65 R110 = 47K,_0402_3: CLABCONF0: =FM-SER
R70 R130 = 47K,_0402_8: CLABCONF0: =FM-SER
R71 R122 = 47K,_0402_7: CLABCONF0: =FM-SER
R50 R78 R97 = 47K,_0402: CLABCONF0: =FM-SER
R83 R117 = 47K,_0402_5: CLABCONF0: =FM-SER
R84 R109 = 47K,_0402_4: CLABCONF0: =FM-SER
R91 R123 = 47K,_0402_6: CLABCONF0: =FM-SER
R147 R164 = 0R,_0402_5: CLABCONF0: =DNP
R149 = 10.5K_1%,0402_3: CLABCONF0: =DNP
R153 = 10.5K_1%,0402_7: CLABCONF0: =FM-SER
R154 = 10.5K_1%,0402_6: CLABCONF0: =DNP
R155 R166 = 10.5K_1%,0402_8: CLABCONF0: =FM-SER
U7-U9 = LTC2872_12: CLABCONF0: =FM-SER; P/N: 116A00060S
U16-U21 = FSA266: CLABCONF0: =FM-SER
R162 = 10.5K_1%,0402_4: CLABCONF0: =DNP
R167 = 10.5K_1%,0402_7: CLABCONF0: =DNP
R54 R170 = 0R,_0402_1: CLABCONF0: =DNP
R172 = 10.5K_1%,0402_1: CLABCONF0: =DNP
R179 = 0R,_0402_6: CLABCONF0: =FM-SER
R180 = 0R,_0402_8: CLABCONF0: =FM-SER
U23 = 74LCX04_sgl_gate_TSSOP-14: CLABCONF0: =DNP
C132 = 100nF,_10V,_X7R,_10%,_0402_34: CLABCONF0: =Y
C133 = 100nF,_10V,_X7R,_10%,_0402_4: CLABCONF0: =Y
C134 = 100nF,_10V,_X7R,_10%,_0402_29: CLABCONF0: =Y
C135 = 100nF,_10V,_X7R,_10%,_0402_28: CLABCONF0: =Y
C136 C138 C140 C142 C172 C174 C176 C177 C203 C207 = 4.7uF,_6.3V,_X5R,_20%,_0603: CLABCONF0: =Y
C137 = 100nF,_10V,_X7R,_10%,_0402_15: CLABCONF0: =Y
C139 = 100nF,_10V,_X7R,_10%,_0402_5: CLABCONF0: =Y
C141 = 100nF,_10V,_X7R,_10%,_0402_36: CLABCONF0: =Y
C143 = 100nF,_10V,_X7R,_10%,_0402_8: CLABCONF0: =Y
C144 = 100nF,_10V,_X7R,_10%,_0402_18: CLABCONF0: =Y
C145 = 100nF,_10V,_X7R,_10%,_0402_9: CLABCONF0: =Y
C146 = 10nF,_25V,_X7R,_10%,_0402_3: CLABCONF0: =Y
C147 = 100nF,_10V,_X7R,_10%,_0402_24: CLABCONF0: =Y
C148 = 100nF,_10V,_X7R,_10%,_0402_16: CLABCONF0: =Y
C149 = Cap.,_18pF,_50V,_NPO,_5%_2: CLABCONF0: =Y
C150 = 100nF,_10V,_X7R,_10%,_0402_35: CLABCONF0: =Y
C151 = 10uF,6.3V,0603,20%X5R_3: CLABCONF0: =Y
C152 = 10uF,6.3V,0603,20%X5R: CLABCONF0: =Y
C153 = Cap.,_18pF,_50V,_NPO,_5%_1: CLABCONF0: =Y
C154 = 100nF,_10V,_X7R,_10%,_0402_14: CLABCONF0: =Y
C155 C156 C191 C192 = 27pF,_50V,_X7R,_10%,_0402: CLABCONF0: =Y; P/N: 151D27000S
C157 C163 C164 C193 C199 C200 = 1uF,X5R,6.3V,0402: CLABCONF0: =Y
C158 = 100nF,_10V,_X7R,_10%,_0402_40: CLABCONF0: =Y
C159 = 10nF,_25V,_X7R,_10%,_0402_2: CLABCONF0: =Y
C160 = 100nF,_10V,_X7R,_10%,_0402_30: CLABCONF0: =Y
C161 = 10nF,_25V,_X7R,_10%,_0402_5: CLABCONF0: =Y
C162 = 100nF,_10V,_X7R,_10%,_0402_17: CLABCONF0: =Y
C165 = 10uF,6.3V,0603,20%X5R_4: CLABCONF0: =Y
C166 = 100nF,_10V,_X7R,_10%,_0402_6: CLABCONF0: =Y
C167 = 10nF,_25V,_X7R,_10%,_0402_4: CLABCONF0: =Y
C168 = 100nF,_10V,_X7R,_10%,_0402: CLABCONF0: =Y
C169 = 100nF,_10V,_X7R,_10%,_0402_33: CLABCONF0: =Y
C170 = 100nF,_10V,_X7R,_10%,_0402_10: CLABCONF0: =Y
C171 = 100nF,_10V,_X7R,_10%,_0402_22: CLABCONF0: =Y
C173 = 100nF,_10V,_X7R,_10%,_0402_12: CLABCONF0: =Y
C175 = 100nF,_10V,_X7R,_10%,_0402_19: CLABCONF0: =Y
C178 = 100nF,_10V,_X7R,_10%,_0402_31: CLABCONF0: =Y
C179 = 100nF,_10V,_X7R,_10%,_0402_26: CLABCONF0: =Y
C180 = 100nF,_10V,_X7R,_10%,_0402_3: CLABCONF0: =Y
C181 = 100nF,_10V,_X7R,_10%,_0402_39: CLABCONF0: =Y
C182 = 10nF,_25V,_X7R,_10%,_0402: CLABCONF0: =Y
C183 = 100nF,_10V,_X7R,_10%,_0402_23: CLABCONF0: =Y
C184 = 100nF,_10V,_X7R,_10%,_0402_13: CLABCONF0: =Y
C185 = 100nF,_10V,_X7R,_10%,_0402_11: CLABCONF0: =Y
C186 = Cap.,_18pF,_50V,_NPO,_5%_3: CLABCONF0: =Y
C187 = 10uF,6.3V,0603,20%X5R_2: CLABCONF0: =Y
C188 = 10uF,6.3V,0603,20%X5R_1: CLABCONF0: =Y
C189 = Cap.,_18pF,_50V,_NPO,_5%: CLABCONF0: =Y
C190 = 100nF,_10V,_X7R,_10%,_0402_37: CLABCONF0: =Y
C194 = 100nF,_10V,_X7R,_10%,_0402_1: CLABCONF0: =Y
C195 = 10nF,_25V,_X7R,_10%,_0402_1: CLABCONF0: =Y
C196 = 100nF,_10V,_X7R,_10%,_0402_32: CLABCONF0: =Y
C197 = 10nF,_25V,_X7R,_10%,_0402_6: CLABCONF0: =Y
C198 = 100nF,_10V,_X7R,_10%,_0402_41: CLABCONF0: =Y
C201 = 10uF,6.3V,0603,20%X5R_5: CLABCONF0: =Y
C202 = 100nF,_10V,_X7R,_10%,_0402_20: CLABCONF0: =Y
C206 = 100nF,_10V,_X7R,_10%,_0402_27: CLABCONF0: =Y
C208 = 100nF,_10V,_X7R,_10%,_0402_7: CLABCONF0: =Y
C209 = 100nF,_10V,_X7R,_10%,_0402_38: CLABCONF0: =Y
C210 = 100nF,_10V,_X7R,_10%,_0402_21: CLABCONF0: =Y
C211 = 100nF,_10V,_X7R,_10%,_0402_2: CLABCONF0: =Y
C212 = 100nF,_10V,_X7R,_10%,_0402_25: CLABCONF0: =Y
L16 = Ferrit_330R@100Mhz,0.2A: CLABCONF0: =Y; P/N: 147D22101S
L17 = Ferrit_330R@100Mhz,0.2A_2: CLABCONF0: =Y; P/N: 147D22101S
L18 L21 = USB_CHOKE_SGL_1: CLABCONF0: =Y
L19 = Ferrit_330R@100Mhz,0.2A_1: CLABCONF0: =Y; P/N: 147D22101S
L20 = Ferrit_330R@100Mhz,0.2A_3: CLABCONF0: =Y; P/N: 147D22101S
P14 = RJ45X2SMT: CLABCONF0: =Y; P/N: 180K01600S
R182 = 12.1K,1%,0402,1_16W: CLABCONF0: =Y
R183 = 2K,1%,0402,1_16W_1: CLABCONF0: =Y
R184 = 0R,_1206: CLABCONF0: =DNP
R185 = 100K,_0402_2: CLABCONF0: =Y
R186 = 100R,1%,0402,1_16W: CLABCONF0: =Y
R187 = 100K,_0402_1: CLABCONF0: =Y
R188 = 0R,_0402_1: CLABCONF0: =Y
R189 = 0R,_0402: CLABCONF0: =Y
R191 = 12.1K,1%,0402,1_16W_1: CLABCONF0: =Y
R193 = 2K,1%,0402,1_16W: CLABCONF0: =Y
R194 = 0R,_1206_1: CLABCONF0: =DNP
R195 = 100K,_0402_3: CLABCONF0: =DNP
R196 = 100K,_0402: CLABCONF0: =Y
RN7 RN8 = RN,0R,8P4R@0805: CLABCONF0: =DNP
RN9 RN10 = RN,10K,8P4R@0805: CLABCONF0: =Y
U24 U30 = MCP2515_20QFN_3: CLABCONF0: =Y
U25 U31 = FT232H_0: CLABCONF0: =Y; P/N: 116A00030S
U26 U32 = ADM3053__0: CLABCONF0: =Y; P/N: 116A00070I
U27 U33 = FSA266: CLABCONF0: =Y
U28 U34 = 93C66-MO-229VCED-2: CLABCONF0: =Y
U29 = 7SZ07D,_buffer: CLABCONF0: =Y; P/N: 106D20070S
U35 = AduM1201_0: CLABCONF0: =Y
X1 X2 = TMP_133032: CLABCONF0: =Y
Y1 Y2 = TMP_0: CLABCONF0: =Y
C72 = 10uF,6.3V,0603,X5R_4: CLABCONF0: =FM-SER
C74 = Cap_1uF,X5R,6.3V,0402: CLABCONF0: =FM-SER
C75 = 10uF,6.3V,0603,X5R_7: CLABCONF0: =DNP
C76 = Cap_1uF,X5R,6.3V,0402: CLABCONF0: =DNP
C77 = 100nF,_10V,_X7R,_10%,_0402_11: CLABCONF0: =DNP
C78 = 22uF,6.3V,X5R_1: CLABCONF0: =FM-SER
C79 = 10uF,6.3V,0603,X5R_3: CLABCONF0: =FM-SER
C81 = 22uF,6.3V,X5R: CLABCONF0: =DNP
C82 = 10uF,6.3V,0603,X5R_2: CLABCONF0: =DNP
C83 = 10uF,6.3V,0603,X5R_1: CLABCONF0: =DNP
C84 = 1nF,_2KV,SMD_1812,_X7R,_10%: CLABCONF0: =DNP
C95 = 4.7uF,_35V,_X7R_X5R,_20%: CLABCONF0: =FM-SER; P/N: 151B47520S
C96 = 4.7uF,_35V,_X7R_X5R,_20%_4: CLABCONF0: =FM-SER; P/N: 151B47520S
C99 = 4.7uF,_35V,_X7R_X5R,_20%_2: CLABCONF0: =FM-SER; P/N: 151B47520S
C101 = 4.7uF,_35V,_X7R_X5R,_20%_5: CLABCONF0: =FM-SER; P/N: 151B47520S
C102 = 4.7uF,_35V,_X7R_X5R,_20%_3: CLABCONF0: =FM-SER; P/N: 151B47520S
C105 = 4.7uF,_35V,_X7R_X5R,_20%_1: CLABCONF0: =FM-SER; P/N: 151B47520S
C112 = 10uF,6.3V,0603,X5R_8: CLABCONF0: =FM-SER
C116 = 10uF,6.3V,0603,X5R_6: CLABCONF0: =FM-SER
C118 = 10uF,6.3V,0603,X5R_5: CLABCONF0: =FM-SER
C129 = 1uF,_16V,_X7R,_20%,_0805_2: CLABCONF0: =FM-SER
C130 = 1uF,_16V,_X7R,_20%,_0805: CLABCONF0: =FM-SER
C131 = 1uF,_16V,_X7R,_20%,_0805_1: CLABCONF0: =FM-SER
FB5 = Ferrite_bead_,_120_Ohm@3A: CLABCONF0: =DNP
L9 = Ind_SIL525-2R2-2.2uH_@_2.1A: CLABCONF0: =FM-SER; Isat: 3.5A; Linit: 6.8uH; P/N: 147A6R801S
L10 = Ind_SIL525-2R2-2.2uH_@_2.1A_1: CLABCONF0: =DNP; Isat: 1.3A; Linit: 6.8uH; P/N: 147A6R800S
L11 = Ind_SIL525-2R2-2.2uH_@_2.1A_2: CLABCONF0: =FM-SER; Isat: 0.5A; Linit: 22uH; P/N: 147A22000S
L12 = Ind_SIL525-2R2-2.2uH_@_2.1A_3: CLABCONF0: =FM-SER; Isat: 0.5A; Linit: 22uH; P/N: 147A22000S
L13 = Ind_SIL525-2R2-2.2uH_@_2.1A_4: CLABCONF0: =FM-SER; Isat: 0.5A; Linit: 22uH; P/N: 147A22000S
MCH1-MCH3 = Mechanical_Hole: CLABCONF0: =DNP; P/N: 3X6HOL
R51 = 40.2k_,1%: CLABCONF0: =DNP
R52 = 0R,_0402: CLABCONF0: =FM-SER
R55 = 36.5K_1%,0402: CLABCONF0: =DNP
U14 = RT8058_,Switcher_,2A: CLABCONF0: =FM-SER
U15 = RT8058_,Switcher_,2A: CLABCONF0: =DNP

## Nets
1V2: C18.1 C26.1 C27.1 C28.1 C29.1 C30.1 C31.1 IC1.D5(VDDCORE0) IC1.D7(VDDCORE1) IC1.D9(VDDCORE2) IC1.D11(VDDCORE3) IC1.D15(FB) IC1.E4(VDDCORE4) IC1.J12(VDDCORE5) IC1.L4(VDDCORE6) IC1.L12(VDDCORE7) IC1.M5(VDDCORE8) IC1.M9(VDDCORE9) IC1.M11(VDDCORE10) L1.2 Q5.3(D)
1V2_EN: R49.2 R54.2 U15.7(EN)
1V2PHY: C8.1 C9.1 C81.1 C82.1 C83.1 IC1.F2(VPA_1V2) IC1.J3(VPB_1V2) L10.2 L15.1 R8.1 R51.1
1V2SW: IC1.F13(VOUT0) IC1.F14(VOUT1) L1.1
3V3_EN: R48.2 R52.2 U14.7(EN)
3V3_IO: C32.1 C33.1 C34.1 C35.1 C36.1 C37.1 IC1.D2(VDDIO1) IC1.H15(VDDIO2) IC1.L2(VDDIO2) IC1.N5(VDDIO2) IC1.N10(VDDIO2) IC1.P15(VDDIO2) IC1.R8(VDDIO2) Q3.3(D) R31.1
3V3_S0_S5: C4.1 C5.1 C10.1 C11.1 C16.1 C17.1 C20.1 C21.1 C22.1 C23.1 C24.1 C25.1 C78.1 C79.1 C80.1 C85.1 C86.1 C87.1 C88.1 C89.2 C90.1 C91.1 C92.1 C93.1 C94.2 C97.2 C98.2 C103.2 C104.2 C106.2 C107.1 C108.1 C109.1 C110.1 C111.1 C112.1 C113.1 C114.1 C115.1 C116.1 C117.1 C118.1 C119.1 C120.1 C121.1 C122.1 C123.2 C124.1 C125.1 C126.1 C127.2 C128.2 C132.1 C133.1 C134.1 C135.1 C140.2 C142.2 C143.1 C145.1 C146.1 C147.1 C151.1 C154.1 C168.1 C169.1 C170.1 C171.1 C176.2 C177.2 C178.1 C181.1 C182.1 C183.1 C187.1 C190.1 C202.2 C203.1 C206.2 C207.1 C208.1 C211.1 C212.1 IC1.A2(VDDIO0) IC1.B14(VDDIO0) IC1.C6(VDDIO0) IC1.C7(VDDIO0) IC1.C8(VDDIO0) IC1.C9(VDDIO0) IC1.D13(VINQ) IC1.E2(VGG1) IC1.E13(VIN0) IC1.E14(VIN1) IC1.H12(VGG5) IC1.M7(VGG3) IC1.M10(VGG4) IC1.N1(VGG2) L9.2 L11.1 L12.1 L13.1 L14.2 L16.2 L17.2 L19.2 L20.2 Q3.2(S) R1.2 R4.2 R5.2 R7.2 R10.1 R11.2 R13.2 R15.2 R22.1 R25.1 R32.2 R50.1 R58.2 R60.2 R64.2 R71.2 R84.2 R97.2 R110.2 R123.2 R135.2 R137.2 R139.2 R148.2 R150.2 R153.2 R155.2 R161.2 R163.2 R166.2 R168.2 R171.2 R173.2 R185.2 R186.2 R187.2 R195.1 RN1.6(RC2) RN1.7(RB2) RN2.5(COM1) RN2.10(COM2) RN3.5(COM1) RN3.10(COM2) RN4.7(RB2) RN4.8(RA2) RN9.1(RA1) RN9.2(RB1) RN9.3(RC1) RN9.4(RD1) RN10.1(RA1) RN10.2(RB1) RN10.3(RC1) RN10.4(RD1) U1.8(VCC) U4.21(VDD) U6.6(ORG) U6.8(Vcc) U7.1(VCC) U7.21(VCC) U7.31(VCC) U7.35(VL) U8.1(VCC) U8.21(VCC) U8.31(VCC) U8.35(VL) U9.1(VCC) U9.21(VCC) U9.31(VCC) U9.35(VL) U16.8(VCC) U17.8(VCC) U18.8(VCC) U19.8(VCC) U20.8(VCC) U21.8(VCC) U22.5(VCC) U23.14(VCC) U24.18(VDD) U25.12(VCCIO) U25.24(VCCIO) U25.39(VCCD) U25.40(VREGIN) U25.46(VCCIO) U26.6(Vio) U28.6(N/C) U28.8(VDD) U30.18(VDD) U31.12(VCCIO) U31.24(VCCIO) U31.39(VCCD) U31.40(VREGIN) U31.46(VCCIO) U32.6(Vio) U34.6(N/C) U34.8(VDD) U35.1(VCC1)
3V3_S5: C166.1 U29.5(VCC)
3V3_TRAN: Q3.1(G) Q4.3(D) R10.2
3V3PHY: C6.1 C7.1 IC1.F3(VP2A_3V3) IC1.K2(VP2B_3V3) L14.1 R7.1
5V_S5: C1.1 C2.1 C3.1 C72.2 C73.1 C74.1 C75.2 C76.1 C77.1 C148.1 C150.1 C152.1 C184.1 C185.1 C188.1 P1.A13(V5SBY) P1.B7(V5SBY) P1.B13(V5SBY) P1.B19(V5SBY) P13.A19(V5SBY) P13.B19(V5SBY) R48.1 R49.1 R56.1 U14.9(VDD) U14.10(PVDD) U14.11(PVDD) U14.12(PVDD) U15.9(VDD) U15.10(PVDD) U15.11(PVDD) U15.12(PVDD) U26.8(VCC) U32.8(VCC)
+12V: P1.A47(VCC_12V) P1.A48(VCC_12V) P1.A49(VCC_12V) P1.A50(VCC_12V) P1.B47(VCC_12V) P1.B48(VCC_12V) P1.B49(VCC_12V) P1.B50(VCC_12V) P13.B48(VCC_12V) P13.B49(VCC_12V) P13.B50(VCC_12V)
GND: C1.2 C2.2 C3.2 C4.2 C5.2 C6.2 C7.2 C8.2 C9.2 C10.2 C11.2 C16.2 C17.2 C18.2 C19.2 C20.2 C21.2 C22.2 C23.2 C24.2 C25.2 C26.2 C27.2 C28.2 C29.2 C30.2 C31.2 C32.2 C33.2 C34.2 C35.2 C36.2 C37.2 C72.1 C73.2 C74.2 C75.1 C76.2 C77.2 C78.2 C79.2 C80.2 C81.2 C82.2 C83.2 C84.2 C85.2 C86.2 C87.2 C88.2 C89.1 C90.2 C91.2 C92.2 C93.2 C94.1 C95.1 C96.1 C97.1 C98.1 C99.1 C101.2 C102.2 C103.1 C104.1 C105.2 C106.1 C107.2 C108.2 C109.2 C110.2 C111.2 C112.2 C113.2 C114.2 C115.2 C116.2 C117.2 C118.2 C119.2 C120.2 C121.2 C122.2 C123.1 C124.2 C125.2 C126.2 C127.1 C128.1 C132.2 C133.2 C134.2 C135.2 C136.1 C137.2 C138.1 C139.2 C140.1 C141.1 C142.1 C143.2 C144.1 C145.2 C146.2 C147.2 C148.2 C149.1 C150.2 C151.2 C152.2 C153.1 C154.2 C155.1 C156.1 C166.2 C167.2 C168.2 C169.2 C170.2 C171.2 C172.1 C173.2 C174.1 C175.2 C176.1 C177.1 C178.2 C179.1 C180.1 C181.2 C182.2 C183.2 C184.2 C185.2 C186.1 C187.2 C188.2 C189.1 C190.2 C191.1 C192.1 C202.1 C203.2 C206.1 C207.2 C208.2 C211.2 C212.2 E1.2 FB5.1 IC1.A1(VSS) IC1.A8(VSS) IC1.A15(VSS) IC1.B15(VSS) IC1.C5(VSS) IC1.C10(VSS) IC1.C11(VSS) IC1.C13(VSSQ_A) IC1.D4(VSS) IC1.D6(VSS) IC1.D8(VSS) IC1.D10(VSS) IC1.D12(VSS) IC1.D14(VSSQ_D) IC1.E1(VSS) IC1.E12(VSS) IC1.E15(VSS) IC1.F1(GND) IC1.F4(VSS) IC1.F12(VSS) IC1.G3(GND) IC1.G12(VSS) IC1.H1(GND) IC1.H2(VSS) IC1.J4(VSS) IC1.K1(VSS) IC1.K4(VSS) IC1.K12(VSS) IC1.L1(PCIe_TEST) IC1.M6(VSS) IC1.M8(VSS) IC1.R1(VSS) P1.A1(GND) P1.A7(GND) P1.A23(GND) P1.A29(GND) P1.A34(GND) P1.A40(GND) P1.B1(GND) P1.B25(GND) P1.B40(GND) P10.A2(B2) P10.A5(B5) P10.B2 P10.B5 P11.A2(B2) P11.A5(B5) P11.B2 P11.B5 P12.A2(B2) P12.A5(B5) P12.B2 P12.B5 P13.A1(GND) P13.A7(GND) P13.A13(GND) P13.A25(GND) P13.A32(GND) P13.A38(GND) P13.A44(GND) P13.A50(GND) P13.B1(GND) P13.B7(GND) P13.B13(GND) P13.B25(GND) P13.B32(GND) P13.B41(GND) Q4.2(S) R2.2 R3.2 R6.2 R12.2 R14.2 R16.2 R17.1 R23.2 R26.2 R28.2 R29.2 R53.2 R55.2 R57.2 R61.2 R70.2 R83.2 R96.2 R109.2 R122.2 R149.2 R154.2 R162.2 R167.2 R172.2 R182.1 R184.1 R191.1 R194.1 R196.2 RN1.5(RD2) RN4.5(RD2) RN5.5(RD2) RN5.6(RC2) RN5.7(RB2) RN5.8(RA2) U1.4(GND) U4.9(VSS) U6.5(Vss) U7.5(GND) U7.18(GND) U7.27(GND) U7.34(GND) U8.5(GND) U8.18(GND) U8.27(GND) U8.34(GND) U9.5(GND) U9.18(GND) U9.27(GND) U9.34(GND) U14.1(PGND) U14.2(PGND) U14.3(PGND) U14.5(GND) U14.17(PAD) U15.1(PGND) U15.2(PGND) U15.3(PGND) U15.5(GND) U15.17(PAD) U16.4(GND) U17.4(GND) U18.4(GND) U19.4(GND) U20.4(GND) U21.4(GND) U22.3(GND) U23.7(GND) U24.8(GND) U24.21(EPAD) U25.4(AGND) U25.9(AGND) U25.10(GND) U25.11(GND) U25.22(GND) U25.23(GND) U25.35(GND) U25.36(GND) U25.41(AGND) U25.42(TEST) U25.47(GND) U25.48(GND) U25.49(EPDA) U26.1(GND1) U26.3(GND1) U26.7(GND1) U26.9(GND1) U26.10(GND1) U28.5(GND) U29.3(GND) U30.8(GND) U30.21(EPAD) U31.4(AGND) U31.9(AGND) U31.10(GND) U31.11(GND) U31.22(GND) U31.23(GND) U31.35(GND) U31.36(GND) U31.41(AGND) U31.42(TEST) U31.47(GND) U31.48(GND) U31.49(EPDA) U32.1(GND1) U32.3(GND1) U32.7(GND1) U32.9(GND1) U32.10(GND1) U34.5(GND) U35.4(GND1) X1.2(GND) X1.4(GND) X2.2(GND) X2.4(GND) Y1.2 Y1.4 Y2.2 Y2.4
GND_C0: P14.A6(SHIELD) R184.2
GND_C1: P14.B6(SHIELD) R194.2
VDD_1: C95.2 U7.20(VDD)
VDD_2: C96.2 U8.20(VDD)
VDD_3: C99.2 U9.20(VDD)
VEE_1: C101.1 U7.39(VEE)
VEE_2: C102.1 U8.39(VEE)
VEE_3: C105.1 U9.39(VEE)
485n232A: RN6.1(R1) U4.1(I/O0.0) U7.13(485/~{232}_1)
485n232B: RN6.2(R2) U4.2(I/O0.1) U7.14(485/~{232}_2)
485n232C: RN6.3(R3) U4.3(I/O0.2) U8.13(485/~{232}_1)
485n232D: RN6.4(R4) U4.4(I/O0.3) U8.14(485/~{232}_2)
485n232E: RN6.6(R5) U4.5(I/O0.4) U9.13(485/~{232}_1)
485n232F: RN6.7(R6) U4.6(I/O0.5) U9.14(485/~{232}_2)
AHnF: RN5.1(RA1) U4.7(I/O0.6) U7.15(H/~{F}) U16.3(OE2) U16.7(OE1) U17.3(OE2) U17.7(OE1)
BHnF: RN5.2(RB1) U4.8(I/O0.7) U8.15(H/~{F}) U18.3(OE2) U18.7(OE1) U21.3(OE2) U21.7(OE1)
BRIDGE_RST: C19.1 IC1.C4(nPOWER_RST) R31.2 R33.2
CAN0_RX: U24.20(RXCAN) U26.4(RxD)
CAN0_TX: U24.19(TXCAN) U26.5(TxD)
CAN1_RX: U30.20(RXCAN) U32.4(RxD)
CAN1_TX: U30.19(TXCAN) U32.5(TxD)
CAN_GND: C157.2 C158.2 C159.2 C160.2 C161.2 C162.2 C163.2 C164.2 C165.2 C193.2 C194.2 C195.2 C196.2 C197.2 C198.2 C199.2 C200.2 C201.2 C209.2 C210.2 P14.A3(CAN_G) P14.A7(CAN_G) P14.B3(CAN_G) P14.B7(CAN_G) U26.11(GND2) U26.13(GND2) U26.16(GND2) U26.18(RS) U26.20(GND2) U27.4(GND) U32.11(GND2) U32.13(GND2) U32.16(GND2) U32.18(RS) U32.20(GND2) U33.4(GND) U35.5(GND2)
CAN_H0: P14.A1(CAN_H) U26.17(CANH)
CAN_H1: P14.B1(CAN_H) U32.17(CANH)
CAN_INT0: P13.A4(DGPU_PRSNT#/RSVD3) U24.11(INT#)
CAN_INT1: P13.A10(DGPU_PWROK/RSVD13) U30.11(INT#)
CAN_L0: P14.A2(CAN_L) U26.15(CANL)
CAN_L1: P14.B2(CAN_L) U32.15(CANL)
CAN_RST: P13.A16(DGPU_SELECT#/RSVD23) R190.2
CAN_RST0#: R188.2 U24.17(RESET#)
CAN_RST1#: R189.2 U30.17(RESET#)
CAN_SUP: P13.A22(DGPU_PWM_SELECT#/RSVD33) R195.2 R196.1 U35.3(INB)
CAN_SUPIS: U27.3(OE2) U27.7(OE1) U33.3(OE2) U33.7(OE1) U35.6(OUTB)
CAN_VCC: C160.1 C161.1 C162.1 C163.1 C164.1 C165.1 C196.1 C197.1 C198.1 C199.1 C200.1 C201.1 C209.1 C210.1 P14.A8(CAN_V) P14.B8(CAN_V) U26.19(Visoin) U27.1(1A) U27.5(2A) U27.8(VCC) U32.19(Visoin) U33.1(1A) U33.5(2A) U33.8(VCC) U35.8(VCC2)
CAN_XI0: C153.2 U24.6(OSC2) X1.1
CAN_XI1: C186.2 U30.7(OSC1) X2.3
CAN_XO0: C149.2 U24.7(OSC1) X1.3
CAN_XO1: C189.2 U30.6(OSC2) X2.1
CANRST: R187.1 R188.1 R189.1 R190.1 U29.4(OUT)
CANRST_TIMER: C167.1 R186.1 U29.2(IN)
CAP_1: C129.2 U7.17(CAP)
CAP_2: C131.2 U8.17(CAP)
CAP_3: C130.2 U9.17(CAP)
CHASSIS: C84.1 FB5.2 MCH1.1 MCH2.1 MCH3.1 P10.13(SHASSIS) P10.14(SHASSIS) P10.15(SHASSIS) P11.13(SHASSIS) P11.14(SHASSIS) P11.15(SHASSIS) P12.13(SHASSIS) P12.14(SHASSIS) P12.15(SHASSIS) P14.15(SHASSIS) P14.16(SHASSIS) P14.17(SHASSIS)
CHnF: RN5.3(RC1) U4.16(I/O1.6) U9.15(H/~{F}) U19.3(OE2) U19.7(OE1) U20.3(OE2) U20.7(OE1)
EEA0: R1.1 R2.1 U1.1(A0)
EEA1: R3.1 R4.1 U1.2(A1)
EEA2: R5.1 R6.1 U1.3(A2)
EECK: IC1.A5(EECK) U6.2(CLK)
EECS: IC1.B6(EECS) U6.1(CS)
EEDI: IC1.A4(EEDO) U6.3(DI)
EEDO: IC1.B5(EEDI) U6.4(DO)
EI_CLKI: IC1.B9(EI_CLK_I) RN4.4(RD1)
EI_D0: IC1.A10(EI_D0) RN3.1(R1)
EI_D1: IC1.B10(EI_D1) RN3.2(R2)
EI_D2: IC1.A11(EI_D2) RN3.3(R3)
EI_D3: IC1.B11(EI_D3) RN3.4(R4)
EI_D4: IC1.A12(EI_D4) RN3.6(R5)
EI_D5: IC1.A13(EI_D5) RN3.8(R7)
EI_D6: IC1.B12(EI_D6) RN3.7(R6)
EI_D7: IC1.A14(EI_D7) RN3.9(R8)
EI_DIR: IC1.A7(EI_DIR) RN4.1(RA1)
EI_RDY: IC1.B8(EI_RDY) RN4.2(RB1)
EXT_PRSNT#: P1.B34(EXT_PRSNT#) RN1.4(RD1)
FB1V2: R51.2 R55.1 U15.4(FB)
FB3.3: R50.2 R53.1 U14.4(FB)
FCH_PCIE_RST#: IC1.B3(nPERST) P1.B31(RESET#) RN1.2(RB1)
FEN1: R135.1 U7.16(FEN)
FEN2: R137.1 U8.16(FEN)
FEN3: R139.1 U9.16(FEN)
FT232_CS#0: RN9.8(RA2) U25.45(EECS) U28.1(CS)
FT232_CS#1: RN10.8(RA2) U31.45(EECS) U34.1(CS)
FT232_REF0: R182.2 U25.5(REF)
FT232_REF1: R191.2 U31.5(REF)
FT232_RST0#: R185.1 U25.34(RESET#) U31.34(RESET#)
FT232_SCK0: RN9.6(RC2) RN9.7(RB2) U25.44(EECLK) U28.2(SK)
FT232_SCK1: RN10.6(RC2) RN10.7(RB2) U31.44(EECLK) U34.2(SK)
FT232_SDI0: R183.2 U25.43(EEDATA) U28.3(DI)
FT232_SDI1: R193.2 U31.43(EEDATA) U34.3(DI)
FT232_SDO0: R183.1 RN9.5(RD2) U28.4(DO)
FT232_SDO1: R193.1 RN10.5(RD2) U34.4(DO)
FT232_SPI_CK0: RN7.8(RA2) U24.12(SCK) U25.13(ADBUS0)
FT232_SPI_CK1: RN8.8(RA2) U30.12(SCK) U31.13(ADBUS0)
FT232_SPI_CS#0: RN7.5(RD2) U24.16(CS#) U25.16(ADBUS3)
FT232_SPI_CS#1: RN8.5(RD2) U30.16(CS#) U31.16(ADBUS3)
FT232_SPI_MISO0: RN7.6(RC2) U24.15(SO) U25.15(ADBUS2)
FT232_SPI_MISO1: RN8.6(RC2) U30.15(SO) U31.15(ADBUS2)
FT232_SPI_MOSI0: RN7.7(RB2) U24.14(SI) U25.14(ADBUS1)
FT232_SPI_MOSI1: RN8.7(RB2) U30.14(SI) U31.14(ADBUS1)
FT232_VCCA0: C141.2 U25.37(VCCA)
FT232_VCCA1: C180.2 U31.37(VCCA)
FT232_VCORE0: C144.2 U25.38(VCORE)
FT232_VCORE1: C179.2 U31.38(VCORE)
FT232_VPHY0: C136.2 C137.1 L16.1 U25.3(VPHY)
FT232_VPHY1: C172.2 C173.1 L19.1 U31.3(VPHY)
FT232_VPLL0: C138.2 C139.1 L17.1 U25.8(VPLL)
FT232_VPLL1: C174.2 C175.1 L20.1 U31.8(VPLL)
FT232_XI0: C155.2 U25.1(OSCI) Y1.1(Y1)
FT232_XI1: C191.2 U31.1(OSCI) Y2.1(Y1)
FT232_XO0: C156.2 U25.2(OSCO) Y1.3(Y3)
FT232_XO1: C192.2 U31.2(OSCO) Y2.3(Y3)
GPIOA0: R11.1 R12.1 U4.18(A0)
GPIOA1: R13.1 R14.1 U4.23(A1)
GPIOA2: R15.1 R16.1 U4.24(A2)
GPIOBG1: IC1.C3(GPIO_0) RN2.1(R1)
GPIOBG2: IC1.B2(GPIO_1) RN2.2(R2)
GPIOBG3: IC1.B1(GPIO_2) RN2.3(R3)
GPIOBG4: IC1.D3(GPIO_3) RN2.4(R4)
GPIOBG5: IC1.C2(GPIO_4) RN2.6(R5)
GPIOBG6: IC1.C1(GPIO_5) RN2.7(R6)
GPIOBG7: IC1.E3(GPIO_6) RN2.8(R7)
GPIOBG8: IC1.D1(GPIO_7) RN2.9(R8)
GPIOEN: IC1.C12(GPIO_EN) R22.2 R28.1
JP_DEF: E1.1 RN6.5(COM1) RN6.10(COM2)
LED: DS1.A(ANODE) R56.2
LOOPBACK: RN5.4(RD1) U4.17(I/O1.7) U7.36(LB) U8.36(LB) U9.36(LB)
LX1V2: L10.1 U15.13(LX) U15.14(LX) U15.15(LX)
LX3.3: L9.1 U14.13(LX) U14.14(LX) U14.15(LX)
MODE: IC1.A6(MODE0) R26.1
nCTS0: IC1.N2(nCTS0) R65.2 U7.38(RB1)
nCTS1: IC1.R3(nCTS1) R78.2 U7.32(RB2)
nCTS2: IC1.N7(nCTS2) R91.2 U8.38(RB1)
nCTS3: IC1.N9(nCTS3) R130.2 U8.32(RB2)
nCTS4: IC1.N13(nCTS4) R104.2 U9.38(RB1)
nCTS5: IC1.M12(nCTS5) R117.2 U9.32(RB2)
nDCD0: IC1.P1(nDCD0) R146.1
nDCD1: IC1.N4(nDCD1) R147.1
nDCD2: IC1.R6(nDCD2) R152.1
nDCD3: IC1.R10(nDCD3) R160.1
nDCD4: IC1.P11(nDCD4) R170.1
nDCD5: IC1.M15(nDCD5) R165.1
nDSR0: IC1.M4(nDSR0) R60.1 R61.1 R68.1 R146.2
nDSR1: IC1.R4(nDSR1) R147.2 R148.1 R149.1 R151.1
nDSR2: IC1.N8(nDSR2) R152.2 R153.1 R154.1 R156.1
nDSR3: IC1.P10(nDSR3) R160.2 R161.1 R162.1 R164.1
nDSR4: IC1.R14(nDSR4) R170.2 R171.1 R172.1 R174.1
nDSR5: IC1.M14(nDSR5) R165.2 R166.1 R167.1 R169.1
nDTR0: IC1.M2(nDTR0) R68.2
nDTR1: IC1.R2(nDTR1) R151.2
nDTR2: IC1.N6(nDTR2) R156.2
nDTR3: IC1.R9(nDTR3) R164.2
nDTR4: IC1.P13(nDTR4) R174.2
nDTR5: IC1.P14(nDTR5) R169.2
nRI0: IC1.M3(nRI0) R64.1
nRI1: IC1.P4(nRI1) R150.1
nRI2: IC1.R7(nRI2) R155.1
nRI3: IC1.N11(nRI3) R163.1
nRI4: IC1.P12(nRI4) R173.1
nRI5: IC1.N15(nRI5) R168.1
nRTS0: IC1.L3(nRTS0) R65.1 R175.2 U7.8(DZ1) U23.1(I)
nRTS1: IC1.P3(nRTS1) R78.1 R176.2 U7.24(DZ2) U23.3(I)
nRTS2: IC1.P6(nRTS2) R91.1 R177.2 U8.8(DZ1) U23.5(I)
nRTS3: IC1.P9(nRTS3) R130.1 R178.2 U8.24(DZ2) U23.9(I)
nRTS4: IC1.R12(nRTS4) R104.1 R179.2 U9.8(DZ1) U23.11(I)
nRTS5: IC1.N14(nRTS5) R117.1 R180.2 U9.24(DZ2) U23.13(I)
PCIE_APU_RX2_N: C12.1 P1.B39(PCIE_RX2-)
PCIE_APU_RX2_P: C13.1 P1.B38(PCIE_RX2+)
PCIE_APU_TX2_N: IC1.G2(RX_N) P1.A39(PCIE_TX2-)
PCIE_APU_TX2_P: IC1.G1(RX_P) P1.A38(PCIE_TX2+)
PCIE_WAKE_UP#: IC1.A3(nWAKE) P1.A37(PCIE_WAKE#)
PG: R32.1 R33.1 R35.1 U22.1(A) U22.2(B)
PGOOD: IC1.C14(POWER_GOOD) Q4.1(G) Q5.1(G) R35.2 R54.1
PWR_GOOD: P1.A46(DEBUG0) U22.4(A+B)
PWR_LED#: DS1.C2(G)(CATHODE2) P1.B46(RSVD)
REF: IC1.H3(REXT) R17.2
RNA: P10.A6(B6) U7.3(B1)
RNB: P10.B6 U7.29(B2)
RNC: P11.A6(B6) U8.3(B1)
RND: P11.B6 U8.29(B2)
RNE: P12.A6(B6) U9.3(B1)
RNF: P12.B6 U9.29(B2)
RPA: P10.A4(B4) U7.2(A1)
RPB: P10.B4 U7.30(A2)
RPC: P11.A4(B4) U8.2(A1)
RPD: P11.B4 U8.30(A2)
RPE: P12.A4(B4) U9.2(A1)
RPF: P12.B4 U9.30(A2)
RTS0: R175.1 U16.2(1B) U16.6(2B) U23.2(12)
RTS1: R176.1 U17.2(1B) U17.6(2B) U23.4(12)
RTS2: R177.1 U18.2(1B) U18.6(2B) U23.6(12)
RTS3: R178.1 U21.2(1B) U21.6(2B) U23.8(12)
RTS4: R179.1 U19.2(1B) U19.6(2B) U23.10(12)
RTS5: R180.1 U20.2(1B) U20.6(2B) U23.12
RXA: IC1.M1(SIN0) U7.37(RA1)
RXB: IC1.P2(SIN1) U7.33(RA2)
RXC: IC1.P5(SIN2) U8.37(RA1)
RXD: IC1.P8(SIN3) U8.33(RA2)
RXE: IC1.R11(SIN4) U9.37(RA1)
RXF: IC1.R15(SIN5) U9.33(RA2)
SHD_BRG: IC1.C15(SHUTDOWN) R29.1
SLP_S3#: DS1.C1(Y)(CATHODE1) P1.B43(SLP) R52.1 RN1.3(RC1)
SMCLK: P1.A14(SMB_CLK) U1.6(SCL) U4.19(SCL)
SMDATA: P1.A15(SMB_DAT) U1.5(SDA) U4.20(SDA)
SPI_CLK: P1.B28(SPI_CLK) RN7.1(RA1) RN8.1(RA1)
SPI_CS: P1.B30(SPI_CS0#) RN8.4(RD1)
SPI_CSOPT: P13.B4(DGPU_PWREN#/RSVD8) RN7.4(RD1)
SPI_MISO: P1.B26(SPI_MISO) RN7.3(RC1) RN8.3(RC1)
SPI_MOSI: P1.B27(SPI_MOSI) RN7.2(RB1) RN8.2(RB1)
SW_1: C129.1 L11.2 U7.19(SW)
SW_2: C131.1 L12.2 U8.19(SW)
SW_3: C130.1 L13.2 U9.19(SW)
TEA: U4.10(I/O1.0) U7.11(TE485_1)
TEB: U4.11(I/O1.1) U7.12(TE485_2)
TEC: U4.12(I/O1.2) U8.11(TE485_1)
TED: U4.13(I/O1.3) U8.12(TE485_2)
TEE: U4.14(I/O1.4) U9.11(TE485_1)
TEF: U4.15(I/O1.5) U9.12(TE485_2)
TEST0: IC1.B7(TEST) R23.1
TNA: P10.A1(B1) U7.6(Z1)
TNB: P10.B1 U7.26(Z2)
TNC: P11.A1(B1) U8.6(Z1)
TND: P11.B1 U8.26(Z2)
TNE: P12.A1(B1) U9.6(Z1)
TNF: P12.B1 U9.26(Z2)
TPA: P10.A3(B3) U7.4(Y1)
TPB: P10.B3 U7.28(Y2)
TPC: P11.A3(B3) U8.4(Y1)
TPD: P11.B3 U8.28(Y2)
TPE: P12.A3(B3) U9.4(Y1)
TPF: P12.B3 U9.28(Y2)
TX2_N: C12.2 IC1.J2(TX_N)
TX2_P: C13.2 IC1.J1(TX_P)
TXA: IC1.K3(SOUT0) U7.7(DY1)
TXB: IC1.N3(SOUT1) U7.25(DY2)
TXC: IC1.R5(SOUT2) U8.7(DY1)
TXD: IC1.P7(SOUT3) U8.25(DY2)
TXE: IC1.R13(SOUT4) U9.7(DY1)
TXF: IC1.N12(SOUT5) U9.25(DY2)
UARTEN: IC1.B13(UART_EN) R25.2
USB_HS7_N: L21.3 P1.B18(USB2_N)
USB_HS7_P: L21.2 P1.B17(USB2_P)
USB_HS7N: L21.4 U31.6(DM)
USB_HS7P: L21.1 U31.7(DP)
USB_HS8_N: L18.3 P1.B15(USB3_N)
USB_HS8_P: L18.2 P1.B14(USB3_P)
USB_HS8N: L18.4 U25.6(DM)
USB_HS8P: L18.1 U25.7(DP)
VISOUT: C157.1 C158.1 C159.1 C193.1 C194.1 C195.1 U26.12(Visoout) U27.2(1B) U27.6(2B) U32.12(Visoout) U33.2(1B) U33.6(2B)
XA_PCIE_CLK_N: IC1.H4(REFCLK_N) P1.B33(PCIE_CLK-)
XA_PCIE_CLK_P: IC1.G4(REFCLK_P) P1.B32(PCIE_CLK+)
N4851426: L15.2 Q5.2(S) R8.2
N5011876: R57.1 U7.9(~{RXEN}_1) U16.5(2A)
N5011883: R58.1 U7.10(DXEN_1) U16.1(1A)
N5019420: R70.1 U7.23(~{RXEN}_2) U17.5(2A)
N5019428: R71.1 U7.22(DXEN_2) U17.1(1A)
N5025430: R83.1 U8.9(~{RXEN}_1) U18.5(2A)
N5025438: R84.1 U8.10(DXEN_1) U18.1(1A)
N5047596: R122.1 U8.23(~{RXEN}_2) U21.5(2A)
N5047604: R123.1 U8.22(DXEN_2) U21.1(1A)
N5092097: R96.1 U9.9(~{RXEN}_1) U19.5(2A)
N5092105: R97.1 U9.10(DXEN_1) U19.1(1A)
N5148546: R109.1 U9.23(~{RXEN}_2) U20.5(2A)
N5148554: R110.1 U9.22(DXEN_2) U20.1(1A)

Not connected (* = marked no-connect by the designer): IC1 A9(EI_CLK_O)* B4(nCLKREQ)*; P1 A2(SATA2_TX+)* A3(SATA2_TX-)* A4(IR_RX)* A5(SATA2_RX+)* A6(SATA2_RX-)* A8(SATA3_TX+)* A9(SATA3_TX-)* A10(SMB_ALRT#)* A11(SATA3_RX+)* A12(SATA3_RX-)* A16(HDA_RST#)* A17(HDA_SYNC)* A18(HDA_BITCLK)* A19(HDA_SDOUT)* A20(HDA_SDIN1)* A21(HDA_SDIN0)* A22(DEBUG3)* A24(USB0_P)* A25(USB0_N)* A26(USB_OC0_1#)* A27(USB1_P)* A28(USB1_N)* A30(LPC_AD0)* A31(LPC_AD1)* A32(LPC_AD2)* A33(LPC_AD3)* A35(PCIE_TX3+)* A36(PCIE_TX3-)* A41(PCIE_TX1+)* A42(PCIE_TX1-)* A43(PWRBTN#)* A44(PCIE_TX0+)* A45(PCIE_TX0-)* B2(SATA0_TX+)* B3(SATA0_TX-)* B4(SATA0_LED)* B5(SATA0_RX+)* B6(SATA0_RX-)* B8(SATA1_RX+)* B9(SATA1_RX-)* B10(DEBUG1)* B11(SATA1_TX+)* B12(SATA1_TX-)* B16(USB_OC_2_3#)* B20(COM2_RX)* B21(COM2_TX)* B22(LPC_SERIRQ)* B23(LPC_CLK)* B24(LPC_FRAME#)* B29(SPI_CS1#)* B35(PCIE_RX3+)* B36(PCIE_RX3-)* B37(SPI_EXT_CNTRL)* B41(PCIE_RX1+)* B42(PCIE_RX1-)* B44(PCIE_RX0+)* B45(PCIE_RX0-)*; P13 A2(PEG_RX0+/RSVD0)* A3(PEG_RX0-/RSVD1)* A5(PEG_RX1+/RSVD4)* A6(PEG_RX1-/RSVD5)* A8(PEG_RX2+/RSVD11)* A9(PEG_RX2-/RSVD12)* A11(PEG_RX3+/RSVD14)* A12(PEG_RX3-/RSVD15)* A14(PEG_RX4+/RSVD21)* A15(PEG_RX4-/RSVD22)* A17(PEG_RX5+/RSVD24)* A18(PEG_RX5-/RSVD25)* A20(PEG_RX6+/RSVD31)* A21(PEG_RX6-/RSVD32)* A23(PEG_RX7+/RSVD34)* A24(PEG_RX7-/RSVD35)* A26(LVDS_A0+/eDP_TX0+)* A27(LVDS_A0-/eDP_TX0-)* A28(LVDS_A1+/eDP_TX1+)* A29(LVDS_A1-/eDP_TX1-)* A30(LVDS_A2+/eDP_TX2+)* A31(LVDS_A2-/eDP_TX2-)* A33(LVDS_A3+/eDP_TX3+)* A34(LVDS_A3-/eDP_TX3-)* A35(LVDS_VDD_EN)* A36(LVDS_ACLK+/eDP_AUX+)* A37(LVDS_ACLK-/eDP_AUX-)* A39(LVDS_CTRL_CLK)* A40(LVDS_CTRL_DATA)* A41(PEG_CLK_REQ#/RSVD42) A42(USB3_TX0+)* A43(USB3_TX0-)* A45(USB3_RX0+) A46(USB3_RX0-) A47(USB_OC_4_5#)* A48(USB4_P) A49(USB4_N) B2(PEG_TX0+/RSVD6)* B3(PEG_TX0-/RSVD7)* B5(PEG_TX1+/RSVD9)* B6(PEG_TX1-/RSVD10)* B8(PEG_TX2+/RSVD16)* B9(PEG_TX2-/RSVD17)* B10(DGPU_HOLD_RST#/RSVD18)* B11(PEG_TX3+/RSVD19)* B12(PEG_TX3-/RSVD20)* B14(PEG_TX4+/RSVD26)* B15(PEG_TX4-/RSVD27)* B16(DGPU_HPD_INTR#/RSVD28)* B17(PEG_TX5+/RSVD29)* B18(PEG_TX5-/RSVD30)* B20(PEG_TX6+/RSVD36)* B21(PEG_TX6-/RSVD37)* B22(SPARE/eDP_HDP)* B23(PEG_TX7+/RSVD38)* B24(PEG_TX7-/RSVD39)* B26(PEG_CLK+/RSVD40) B27(PEG_CLK-/RSVD41) B28(LVDS_BKLT_CTRL)* B29(COM1_DCR)* B30(COM1_TX)* B31(COM1_DCD)* B33(COM1_DTR)* B34(COM1_RTS)* B35(COM1_RX)* B36(COM1_CTS)* B37(COM1_RI)* B38(LVDS_BKLT_EN)* B39(LVDS_I2C_CLK)* B40(LVDS_I2C_DAT)* B42(USB3_TX1+)* B43(USB3_TX1-)* B44(NC)* B45(USB3_RX1+)* B46(USB3_RX1-)* B47(SPARE0)*; P14 A4(NC)* A5(NC)* B4(NC)* B5(NC)*; RN1 1(RA1)* 8(RA2)*; RN4 3(RC1)* 6(RC2)*; RN6 8(R7)* 9(R8)*; U1 7(WP)*; U4 22(\\~{IN}T)*; U6 7(NC)*; U14 6(NC)* 8(NC)* 16(NC)*; U15 6(NC)* 8(NC)* 16(NC)*; U24 1(CLKOUT)* 2(TX0RTS#)* 3(TX1RTS#)* 4(NC)* 5(TX2RTS#)* 9(RX1BF#)* 10(RX0BF#)* 13(NC)*; U25 17(ADBUS4)* 18(ADBUS5)* 19(ADBUS6)* 20(ADBUS7)* 21(ACBUS0)* 25(ACBUS1)* 26(ACBUS2)* 27(ACBUS3)* 28(ACBUS4)* 29(ACBUS5)* 30(ACBUS6)* 31(ACBUS7)* 32(ACBUS8)* 33(ACBUS9)*; U26 2(NC)* 14(Vref)*; U28 7(N/C)*; U30 1(CLKOUT)* 2(TX0RTS#)* 3(TX1RTS#)* 4(NC)* 5(TX2RTS#)* 9(RX1BF#)* 10(RX0BF#)* 13(NC)*; U31 17(ADBUS4)* 18(ADBUS5)* 19(ADBUS6)* 20(ADBUS7)* 21(ACBUS0)* 25(ACBUS1)* 26(ACBUS2)* 27(ACBUS3)* 28(ACBUS4)* 29(ACBUS5)* 30(ACBUS6)* 31(ACBUS7)* 32(ACBUS8)* 33(ACBUS9)*; U32 2(NC)* 14(Vref)*; U34 7(N/C)*; U35 2(OUTA)* 7(INA)*

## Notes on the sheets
sheet 1
- FM-SER rev 1.1
- PAGE
- FUNCTION
- 01
- INDEX
- 02
- EXT CONNECTORS
- 03
- COM_PCIe_BRIDGE
- 04
- RS232/RS485 PHY
- 05
- RS232/RS485 PHY
- 06
- CAN-Bus
- 07
- POWER
- FACE MODULE FOR:
  FITPC-3 & INTENC-PC
  COM x 6
  CANBus x 2
sheet 2
- PU ON MB
- DNP
- PU ON MB
- DNP
- SMB:A8h-A9h
- DNP
- USB
- PCIe
- SYSTEM
- SPI
- CAN GPIOS
- DNP
- MSBus
sheet 3
- AUX. GPIO CONTROLLER
- DNP
- DNP
- SMB:4Ch-4Dh
- DNP
sheet 4
- CAN ISOLATION, POWER & PHY
- DNP
- DNP
- OD
- CAN ISOLATION, POWER & PHY
- DNP
- DNP
- DNP
- SPI
- GPIOS
- DNP
sheet 5
- POWER
  3.3V UP TO 2A
- POWER
  1.2V UP TO 1.3A
- DNP
- DNP
sheet 6
- DNP
- DNP
- DNP
- DNP
- RS232
- RS485
- RS422H
- TN[A-F]
- RTS
- TNA
- DATA-
- TP[A-F]
- TX
- TPA
- DATA+
- RP[A-F]
- RX
- RPA
- -
- DNP
- RN[A-F]
- CTS
- RNA
- -
- DNP
- DNP
- DNP
- DNP
- DNP
- DNP
- DNP
sheet 7
- DNP
- DNP
- DNP
- DNP
- RS232
- RS485
- RS422H
- TN[A-F]
- RTS
- TNA
- DATA-
- DNP
- TP[A-F]
- TX
- TPA
- DATA+
- DNP
- DNP
- RP[A-F]
- RX
- RPA
- -
- RN[A-F]
- CTS
- RNA
- -
- DNP
- DNP
- DNP
- DNP
- DNP
